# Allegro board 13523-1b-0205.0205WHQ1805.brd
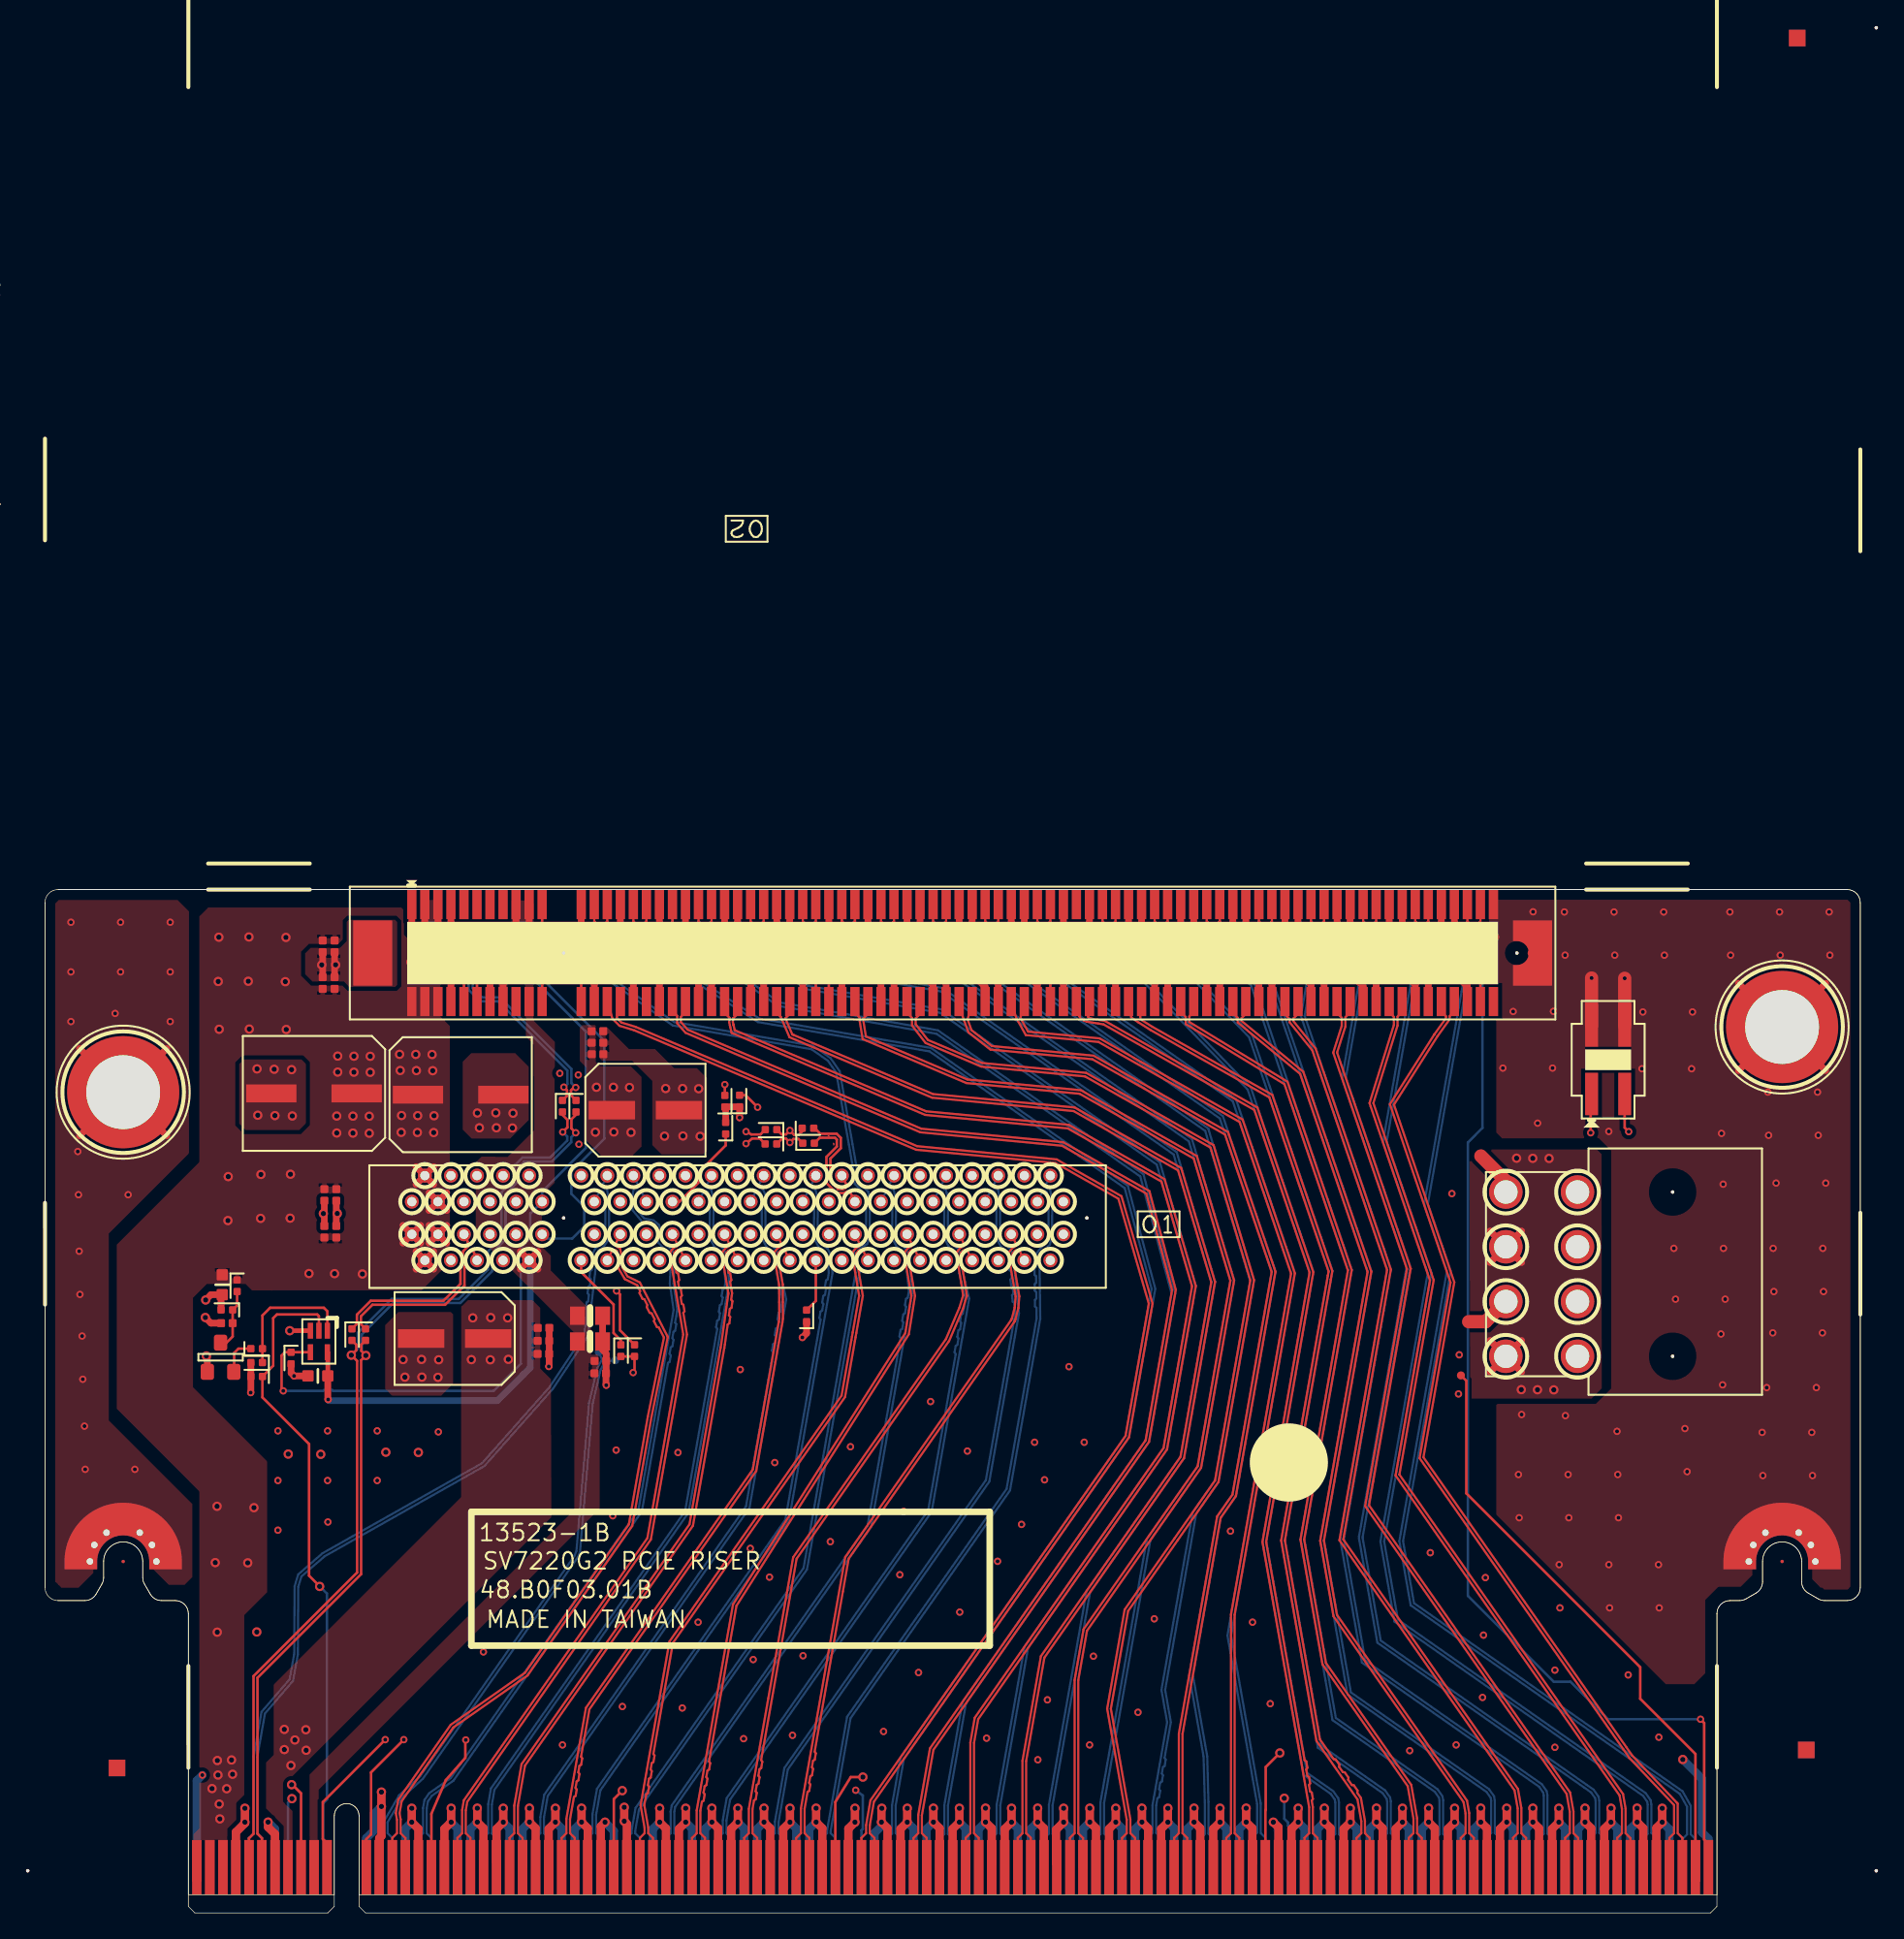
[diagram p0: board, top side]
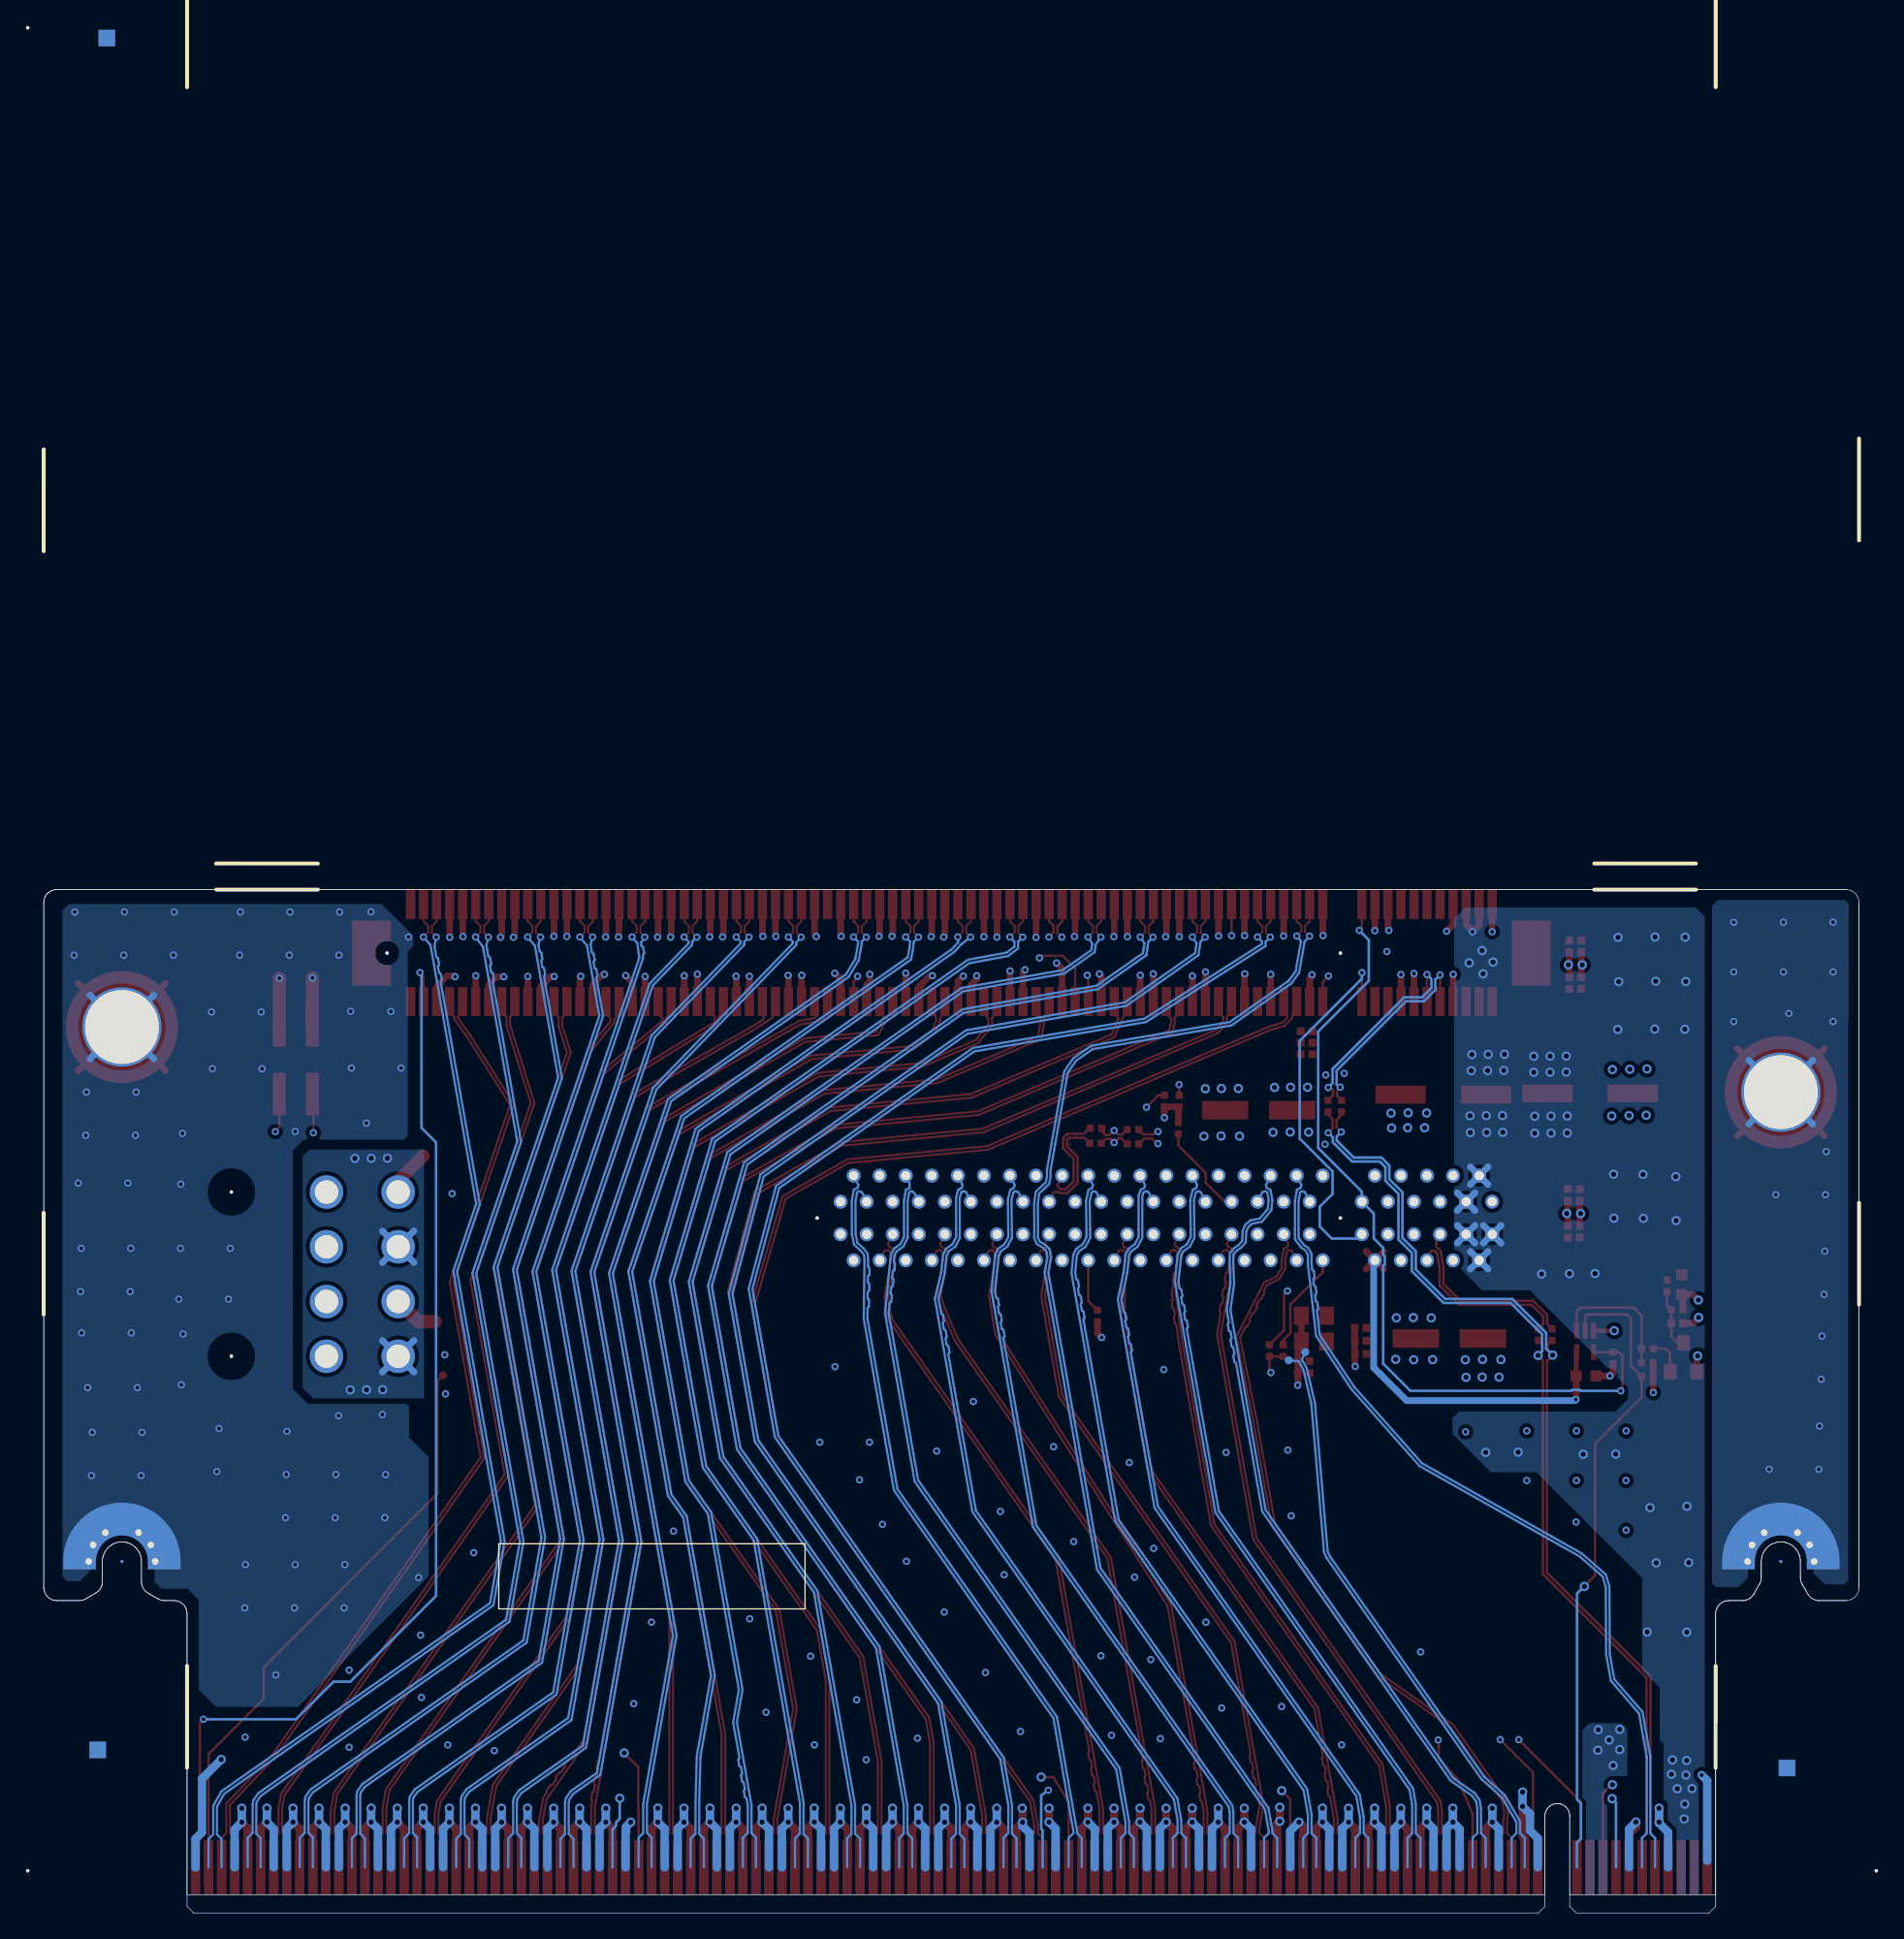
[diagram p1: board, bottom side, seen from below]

Outline 139.3 x 78.5 mm; copper layers: TOP, L2GND, L3, L4VCC, L5GND, BOTTOM. Coordinates in mm from the lower left corner of the outline.
Outline path: 0,77.5 0,24.96 ; 0,77.5 arc(0.29,78.21) 1,78.5 ; 0,77.5 0,24.96 ; 0,24.96 arc(0.29,24.25) 1,23.96 ; 1,78.5 138.3,78.5 ; 1,78.5 138.3,78.5 ; 138.3,78.5 arc(139.01,78.21) 139.3,77.5 ; 138.3,78.5 arc(139.01,78.21) 139.3,77.5 ; 1,23.96 3.06,23.96 ; 1,23.96 3.06,23.96 ; 3.06,23.96 arc(3.56,24.09) 3.92,24.46 ; 3.06,23.96 arc(3.56,24.09) 3.92,24.46 ; 3.92,24.46 4.37,25.23 ; 3.92,24.46 4.37,25.23 ; 4.37,25.23 arc(4.47,25.47) 4.5,25.73 ; 4.37,25.23 arc(4.47,25.47) 4.5,25.73 ; 4.5,26.96 4.5,25.73 ; 4.5,26.96 arc(6,28.46) 7.5,26.96 ; 4.5,26.96 arc(6,28.46) 7.5,26.96 ; 4.5,26.96 4.5,25.73 ; 7.5,26.96 7.5,25.73 ; 7.5,26.96 7.5,25.73 ; 7.5,25.73 arc(7.53,25.47) 7.63,25.23 ; 7.5,25.73 arc(7.53,25.47) 7.63,25.23 ; 7.63,25.23 8.08,24.46 ; 7.63,25.23 8.08,24.46 ; 8.08,24.46 arc(8.44,24.09) 8.94,23.96 ; 8.08,24.46 arc(8.44,24.09) 8.94,23.96 ; 8.94,23.96 10,23.96 ; 8.94,23.96 10,23.96 ; 10,23.96 arc(10.71,23.67) 11,22.96 ; 10,23.96 arc(10.71,23.67) 11,22.96 ; 11,22.96 11,1.4 22.2,1.4 22.2,7.45 ; 11,22.96 11,0.5 11.5,0 21.7,0 22.2,0.5 22.2,7.45 ; 22.2,7.45 arc(23.15,8.4) 24.1,7.45 ; 22.2,7.45 arc(23.15,8.4) 24.1,7.45 ; 24.1,7.45 24.1,1.4 128.3,1.4 128.3,22.96 ; 24.1,7.45 24.1,0.5 24.6,0 127.8,0 128.3,0.5 128.3,22.96 ; 128.3,22.96 arc(128.59,23.67) 129.3,23.96 ; 128.3,22.96 arc(128.59,23.67) 129.3,23.96 ; 129.3,23.96 130.03,23.96 ; 129.3,23.96 130.03,23.96 ; 130.03,23.96 arc(130.29,23.99) 130.53,24.09 ; 130.03,23.96 arc(130.29,23.99) 130.53,24.09 ; 130.53,24.09 131.3,24.54 ; 130.53,24.09 131.3,24.54 ; 131.3,24.54 arc(131.67,24.9) 131.8,25.4 ; 131.3,24.54 arc(131.67,24.9) 131.8,25.4 ; 131.8,26.96 131.8,25.4 ; 131.8,26.96 arc(133.3,28.46) 134.8,26.96 ; 131.8,26.96 arc(133.3,28.46) 134.8,26.96 ; 131.8,26.96 131.8,25.4 ; 134.8,26.96 134.8,25.4 ; 134.8,26.96 134.8,25.4 ; 134.8,25.4 arc(134.93,24.9) 135.3,24.54 ; 134.8,25.4 arc(134.93,24.9) 135.3,24.54 ; 135.3,24.54 136.07,24.09 ; 135.3,24.54 136.07,24.09 ; 136.07,24.09 arc(136.31,23.99) 136.57,23.96 ; 136.07,24.09 arc(136.31,23.99) 136.57,23.96 ; 136.57,23.96 138.3,23.96 ; 136.57,23.96 138.3,23.96 ; 138.3,23.96 arc(139.01,24.25) 139.3,24.96 ; 138.3,23.96 arc(139.01,24.25) 139.3,24.96 ; 139.3,77.5 139.3,24.96 ; 139.3,77.5 139.3,24.96

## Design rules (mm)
constraint set DEFAULT: min track width 0.127, pair gap 0.102
net group POWER-40: nets P5V-1 P5V-2
net group 50OHM_SIGNAL-MW: nets PCIE_CPRSNT_N PCIE_SLOT0_CPRSNT1_N PCIE_SLOT0_CPRSNT2_N PCIE_SLOT1_CPRSNT1_N PCIE_SLOT1_CPRSNT2_N PCIE_SLOT1_CPRSNT3_N PCIE_WAKE_N SLOT0_CONFIG SLOT0_ID_0 SLOT0_ID_1 SLOT1_CONFIG SLOT1_ID_0 SLOT1_ID_1
net group CRITICAL_50OHM_SIGNAL-MW: nets PCH_PLTRST_N PERST_LAT_N PERST_N RESET_IN RESET_O
net group I2C-MW: nets LAN_SMB_ALERT_N S0_SMB_ALERT_B12_N S1_SMB_ALERT_B12_N

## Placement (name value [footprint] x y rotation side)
C1  SCD1U25V2KX-GP  [C402H22]  22.35 52.26 180 top
C2  SCD1U25V2KX-GP  [C402H22]  21.44 55.08 0 top
C3  SCD1U25V2KX-GP  [C402H22]  21.44 52.26 180 top
C4  SCD1U25V2KX-GP  [C402H22]  22.35 55.08 0 top
C5  SCD1U16V2KX-3GP  [C402H22]  38.25 44.87 90 top
C6  SCD1U16V2KX-3GP  [C402H22]  38.24 42.88 90 top
C7  SCD1U16V2KX-3GP  [C402H22]  38.25 43.88 90 top
C8  SC10U6D3V5KX-4GP  [C805H58]  41.82 43.83 90 top
C9  SCD1U16V2KX-3GP  [C402H22]  42.62 42.34 90 top
C10  SCD1U25V2KX-GP  [C402H22]  21.31 74.15 0 top
C11  SCD1U25V2KX-GP  [C402H22]  22.23 74.15 0 top
C12  SCD1U25V2KX-GP  [C402H22]  21.31 71.33 180 top
C13  SCD1U25V2KX-GP  [C402H22]  22.23 71.33 180 top
C14  SCD1U16V2KX-3GP  [C402H22]  42.39 67.63 90 top
C15  SCD1U16V2KX-3GP  [C402H22]  42.4 65.87 90 top
C16  SCD1U16V2KX-3GP  [C402H22]  42.4 66.75 90 top
C17  SC10U6D3V5KX-4GP  [C805H58]  41.83 45.81 90 top
C18  SCD1U16V2KX-3GP  [C402H22]  42.61 41.39 90 top
C19  SCD01U16V2KX-L1-GP  [C402H22]  13.96 45.24 270 top
C20  SCD1U25V3KX-GP  [C603H36]  20.94 41.19 270 top
C21  SCD1U25V3KX-GP  [C603H36]  13.6 48.19 0 top
CFGCN1  AMP-CONN4A-2-GP  [G800MR594018EU]  119.95 65.45 180 top
CN1  TYCO-CONN98-4R-6-GP  [2-1612163-3]  39.8 53.31 0 top
CN2  PCISLT164-64-GP  [G630FAA2621EU]  39.8 73.63 0 top
CN3  ALP-CONN8B-GP  [C23106-108C0-L]  124.9 49 90 top
GF1  GF-PCIE-230P-GP  [GF-PCIE-230P]  23.15 1.4 0 top
H1  STFT339B239R223H453-GP  [STFT339B239R223H453]  133.3 67.96 0 top
H2  STFT339B239R223H453-GP  [STFT339B239R223H453]  6 62.96 0 top
H3  GEN276X162R197X296-6-F-A-GP  [GEN276X162R197X296-6-F-A]  133.3 26.96 0 top
H4  GEN276X162R197X296-6-F-A-GP  [GEN276X162R197X296-6-F-A]  6 26.96 0 top
NOREF  -  [unnamed]  135.16 12.5 0 top
NOREF#2  -  [unnamed]  140.53 144.61 0 top
NOREF#3  -  [#2]  0 23.96 0 top
NOREF#4  -  [#2]  0 23.96 0 top
NOREF#5  -  [#2]  95.45 34.55 0 top
NOREF#6  -  [unnamed]  -1.32 3.24 0 top
NOREF#7  -  [unnamed]  5.53 11.12 0 top
NOREF#8  -  [#2]  -5 138.58 0 top
NOREF#9  -  [unnamed]  134.46 143.82 0 top
NOREF#10  -  [#2]  85.46 52.82 0 top
NOREF#11  -  [#2]  0 23.96 0 top
NOREF#12  -  [#2]  53.84 106.18 180 top
NOREF#13  -  [#2]  0 23.96 0 top
NOREF#14  -  [unnamed]  140.53 3.24 0 top
NOREF#15  -  [#2]  5.61 149.39 0 top
NOREF#16  -  [#2]  0 23.96 0 top
NOREF#17  -  [#2]  0 23.96 0 top
NOREF#18  -  [unnamed]  135.16 12.5 180 bottom
NOREF#19  -  [unnamed]  5.53 11.12 180 bottom
NOREF#20  -  [unnamed]  134.46 143.82 180 bottom
R1  4K7R2D-GP  [R402H16]  14.74 48.11 0 top
R2  1K8R2D-GP  [R402H16]  13.96 46.26 270 top
R3  0R2J-2-GP  [R402H16]  16.24 43.29 90 top
R4  100KR2F-L1-GP  [R402H16]  16.24 42.22 270 top
R5  100KR2F-L1-GP  [R402H16]  16.24 41.15 270 top
R6  100KR2F-L1-GP  [R402H16]  18.88 42.57 0 top
R7  100R2J-L-GP  [R402H15]  52.23 60.2 180 top
R8  100R2J-L-GP  [R402H15]  58.44 45.8 180 top
R9  100R2J-L-GP  [R402H15]  52.17 62.27 180 top
R10  100R2J-L-GP  [R402H15]  53.3 62.28 180 top
RE1  0R2J-2-GP  [R402H16]  23.56 44.36 0 top
RE2  0R2J-2-GP  [R402H16]  58.55 60.19 90 top
RE3  0R2J-2-GP  [R402H16]  58.59 59.04 90 top
RE4  0R2J-2-GP  [R402H16]  44.19 43.13 0 top
RE5  0R2J-2-GP  [R402H16]  55.72 60.09 270 top
RE6  0R2J-2-GP  [R402H16]  55.71 58.99 270 top
RE7  0R2J-2-GP  [R402H16]  24.6 44.36 0 top
RE8  0R2J-2-GP  [R402H16]  45.24 43.14 0 top
RE9  0R2J-2-GP  [R402H16]  40.75 61.89 0 top
RE10  0R2J-2-GP  [R402H16]  39.71 61.89 0 top
TC1  SE270U16VM-2-GP  [SE391427H276]  20.64 62.86 270 top
TC2  SE220U6D3VM-8GP  [SE331721H237]  31.44 44.06 270 top
TC3  SE270U16VM-2-GP  [SE391427H276]  31.9 62.77 90 top
TC4  SE220U6D3VM-8GP  [SE331721H237]  46.07 61.58 90 top
TP1  -  [TPAD24]  42.49 43.02 180 bottom
TP2  -  [TPAD24]  43.76 42.39 180 bottom
TP3  -  [TPAD24]  108.66 41.23 0 top
TP4  -  [TPAD24]  110.19 58.06 0 top
TP5  -  [TPAD24]  109.25 45.35 0 top
U1  TPS3809K33-2-GP  [SOT-23-1H58]  13.47 42.63 0 top
U8  SNLVC1G08DCKRG4-GP  [SC70-5H44]  21.02 43.84 0 top

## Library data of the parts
C1-C4 C10-C13 = C402H22: tolerance: 78.10422.5FL
C5-C7 C9 C14-C16 C18 = C402H22: tolerance: 78.10421.2FL
C8 C17 = C805H58: tolerance: 78.10620.21L
C19 = C402H22: tolerance: 78.10321.L0L
C20 C21 = C603H36: tolerance: 78.10422.2BL
CFGCN1 = G800MR594018EU: tolerance: 21.D0408.202
CN1 = 2-1612163-3: tolerance: 20.50446.098
CN2 = G630FAA2621EU: tolerance: 20.C0083.164
CN3 = C23106-108C0-L: tolerance: 20.82113.008
GF1 = GF-PCIE-230P: tolerance: ZZ.GF001.711; alternate symbols: (TOP:GF-PCIE-230P)
H1 H2 = STFT339B239R223H453: tolerance: ZZ.SCREW.601
H3 H4 = GEN276X162R197X296-6-F-A: tolerance: ZZ.SCREW.511
R1 = R402H16: tolerance: 64.47016.6DL
R2 = R402H16: tolerance: 64.18016.6DL
R3 RE1-RE10 = R402H16: tolerance: 63.R0034.1DL
R4-R6 = R402H16: tolerance: 64.10035.6DL
R7-R10 = R402H15: tolerance: 63.10134.L0L
TC1 TC3 = SE391427H276: tolerance: 77.52771.01L
TC2 TC4 = SE331721H237: tolerance: 79.22710.E0L
TP1-TP5 = TPAD24: tolerance: ZZ.PAD24.001
U1 = SOT-23-1H58: tolerance: 74.03809.07B
U8 = SC70-5H44: tolerance: 73.01G08.DHG

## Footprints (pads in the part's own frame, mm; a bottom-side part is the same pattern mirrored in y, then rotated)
2-1612163-3
  round 0.254 hole 2.362 unplated: (0,0) (40.15,0)
  round 1.067 hole 0.711: A1(-11.65,1.25) A2(-10.65,3.25) A3(-9.649,1.25) A4(-8.65,3.25) A5(-7.65,1.25) A6(-6.65,3.25) A7(-5.65,1.25) A8(-4.649,3.25) A9(-3.65,1.25) A10(-2.65,3.25) A11(-1.65,1.25) A12(1.35,3.25) A13(2.349,1.25) A14(3.35,3.25) A15(4.35,1.25) A16(5.351,3.25) A17(6.35,1.25) A18(7.349,3.25) A19(8.35,1.25) A20(9.35,3.25) A21(10.351,1.25) A22(11.35,3.25) A23(12.349,1.25) A24(13.35,3.25) A25(14.35,1.25) A26(15.35,3.25) A27(16.35,1.25) A28(17.349,3.25) A29(18.35,1.25) A30(19.35,3.25) A31(20.35,1.25) A32(21.35,3.25) A33(22.349,1.25) A34(23.35,3.25) A35(24.35,1.25) A36(25.35,3.25) A37(26.35,1.25) A38(27.349,3.25) A39(28.35,1.25) A40(29.35,3.25) A41(30.35,1.25) A42(31.35,3.25) A43(32.349,1.25) A44(33.35,3.25) A45(34.35,1.25) A46(35.35,3.25) A47(36.35,1.25) A48(37.349,3.25) A49(38.35,1.25) B1(-11.65,-1.25) B2(-10.65,-3.25) B3(-9.649,-1.25) B4(-8.65,-3.25) B5(-7.65,-1.25) B6(-6.65,-3.25) B7(-5.65,-1.25) B8(-4.649,-3.25) B9(-3.65,-1.25) B10(-2.65,-3.25) B11(-1.65,-1.25) B12(1.35,-3.25) B13(2.349,-1.25) B14(3.35,-3.25) B15(4.35,-1.25) B16(5.351,-3.25) B17(6.35,-1.25) B18(7.349,-3.25) B19(8.35,-1.25) B20(9.35,-3.25) B21(10.351,-1.25) B22(11.35,-3.25) B23(12.349,-1.25) B24(13.35,-3.25) B25(14.35,-1.25) B26(15.35,-3.25) B27(16.35,-1.25) B28(17.349,-3.25) B29(18.35,-1.25) B30(19.35,-3.25) B31(20.35,-1.25) B32(21.35,-3.25) B33(22.349,-1.25) B34(23.35,-3.25) B35(24.35,-1.25) B36(25.35,-3.25) B37(26.35,-1.25) B38(27.349,-3.25) B39(28.35,-1.25) B40(29.35,-3.25) B41(30.35,-1.25) B42(31.35,-3.25) B43(32.349,-1.25) B44(33.35,-3.25) B45(34.35,-1.25) B46(35.35,-3.25) B47(36.35,-1.25) B48(37.349,-3.25) B49(38.35,-1.25)
C402H22
  custom 0.152x0.152 smd: 1(0,0.445) 2(0,-0.445)
C603H36
  custom 0.216x0.216 smd: 1(0,0.762) 2(0,-0.762)
C805H58
  rect 1.397x1.143 smd: 1(0,0.965) 2(0,-0.965)
C23106-108C0-L
  round 0.254 hole 3.023 unplated: (-6.3,0) (6.3,0)
  round 2.565 hole 1.803: 1(6.3,7.3) 2(2.1,7.3) 3(-2.1,7.3) 4(-6.3,7.3) 5(6.3,12.8) 6(2.1,12.8) 7(-2.1,12.8) 8(-6.3,12.8)
G630FAA2621EU
  round 0.254 hole 1.219 unplated: (0,0) (73.15,0)
  rect 2.997x5.004 smd: 165(-14.65,0)
  custom 0.749x0.749 smd: 166(74.35,0)
  rect 0.711x2.235 smd: A1(-11.65,3.718) A2(-10.65,3.718) A3(-9.65,3.718) A4(-8.65,3.718) A5(-7.65,3.718) A6(-6.65,3.718) A7(-5.65,3.718) A8(-4.65,3.718) A9(-3.65,3.718) A10(-2.65,3.718) A11(-1.65,3.718) A12(1.35,3.718) A13(2.35,3.718) A14(3.35,3.718) A15(4.35,3.718) A16(5.35,3.718) A17(6.35,3.718) A18(7.35,3.718) A19(8.35,3.718) A20(9.35,3.718) A21(10.35,3.718) A22(11.35,3.718) A23(12.35,3.718) A24(13.35,3.718) A25(14.35,3.718) A26(15.35,3.718) A27(16.35,3.718) A28(17.35,3.718) A29(18.35,3.718) A30(19.35,3.718) A31(20.35,3.718) A32(21.35,3.718) A33(22.35,3.718) A34(23.35,3.718) A35(24.35,3.718) A36(25.35,3.718) A37(26.35,3.718) A38(27.35,3.718) A39(28.35,3.718) A40(29.35,3.718) A41(30.35,3.718) A42(31.35,3.718) A43(32.35,3.718) A44(33.35,3.718) A45(34.35,3.718) A46(35.35,3.718) A47(36.35,3.718) A48(37.35,3.718) A49(38.35,3.718) A50(39.35,3.718) A51(40.35,3.718) A52(41.35,3.718) A53(42.35,3.718) A54(43.35,3.718) A55(44.35,3.718) A56(45.35,3.718) A57(46.35,3.718) A58(47.35,3.718) A59(48.35,3.718) A60(49.35,3.718) A61(50.35,3.718) A62(51.35,3.718) A63(52.35,3.718) A64(53.35,3.718) A65(54.35,3.718) A66(55.35,3.718) A67(56.35,3.718) A68(57.35,3.718) A69(58.35,3.718) A70(59.35,3.718) A71(60.35,3.718) A72(61.35,3.718) A73(62.35,3.718) A74(63.35,3.718) A75(64.35,3.718) A76(65.35,3.718) A77(66.35,3.718) A78(67.35,3.718) A79(68.35,3.718) A80(69.35,3.718) A81(70.35,3.718) A82(71.35,3.718) B1(-11.65,-3.718) B2(-10.65,-3.718) B3(-9.65,-3.718) B4(-8.65,-3.718) B5(-7.65,-3.718) B6(-6.65,-3.718) B7(-5.65,-3.718) B8(-4.65,-3.718) B9(-3.65,-3.718) B10(-2.65,-3.718) B11(-1.65,-3.718) B12(1.35,-3.718) B13(2.35,-3.718) B14(3.35,-3.718) B15(4.35,-3.718) B16(5.35,-3.718) B17(6.35,-3.718) B18(7.35,-3.718) B19(8.35,-3.718) B20(9.35,-3.718) B21(10.35,-3.718) B22(11.35,-3.718) B23(12.35,-3.718) B24(13.35,-3.718) B25(14.35,-3.718) B26(15.35,-3.718) B27(16.35,-3.718) B28(17.35,-3.718) B29(18.35,-3.718) B30(19.35,-3.718) B31(20.35,-3.718) B32(21.35,-3.718) B33(22.35,-3.718) B34(23.35,-3.718) B35(24.35,-3.718) B36(25.35,-3.718) B37(26.35,-3.718) B38(27.35,-3.718) B39(28.35,-3.718) B40(29.35,-3.718) B41(30.35,-3.718) B42(31.35,-3.718) B43(32.35,-3.718) B44(33.35,-3.718) B45(34.35,-3.718) B46(35.35,-3.718) B47(36.35,-3.718) B48(37.35,-3.718) B49(38.35,-3.718) B50(39.35,-3.718) B51(40.35,-3.718) B52(41.35,-3.718) B53(42.35,-3.718) B54(43.35,-3.718) B55(44.35,-3.718) B56(45.35,-3.718) B57(46.35,-3.718) B58(47.35,-3.718) B59(48.35,-3.718) B60(49.35,-3.718) B61(50.35,-3.718) B62(51.35,-3.718) B63(52.35,-3.718) B64(53.35,-3.718) B65(54.35,-3.718) B66(55.35,-3.718) B67(56.35,-3.718) B68(57.35,-3.718) B69(58.35,-3.718) B70(59.35,-3.718) B71(60.35,-3.718) B72(61.35,-3.718) B73(62.35,-3.718) B74(63.35,-3.718) B75(64.35,-3.718) B76(65.35,-3.718) B77(66.35,-3.718) B78(67.35,-3.718) B79(68.35,-3.718) B80(69.35,-3.718) B81(70.35,-3.718) B82(71.35,-3.718)
G800MR594018EU
  rect 0.991x3.251 smd: 1(1.27,2.625) 2(1.27,-2.625) 3(-1.27,2.625) 4(-1.27,-2.625)
GEN276X162R197X296-6-F-A
  round 0.254 hole 0.025 unplated: (0,0)
  round 0.864 hole 0.508: 1(2.55,0) 2(2.21,1.27) 3(1.27,2.21) 4(-1.28,2.21) 5(-2.21,1.27) 6(-2.55,0)
GF-PCIE-230P
  rect 0.711x3.2 smd: A1(-11.5,2.591) B114(103.5,2.591)
  rect 0.711x4.191 smd: A2(-10.5,2.095) A3(-9.5,2.095) A4(-8.5,2.095) A5(-7.5,2.095) A6(-6.5,2.095) A7(-5.5,2.095) A8(-4.5,2.095) A9(-3.5,2.095) A10(-2.5,2.095) A11(-1.5,2.095) A12(1.5,2.095) A13(2.5,2.095) A14(3.5,2.095) A15(4.5,2.095) A16(5.5,2.095) A17(6.5,2.095) A18(7.5,2.095) A19(8.5,2.095) A20(9.5,2.095) A21(10.5,2.095) A22(11.5,2.095) A23(12.5,2.095) A24(13.5,2.095) A25(14.5,2.095) A26(15.5,2.095) A27(16.5,2.095) A28(17.5,2.095) A29(18.5,2.095) A30(19.5,2.095) A31(20.5,2.095) A32(21.5,2.095) A33(22.5,2.095) A34(23.5,2.095) A35(24.5,2.095) A36(25.5,2.095) A37(26.5,2.095) A38(27.5,2.095) A39(28.5,2.095) A40(29.5,2.095) A41(30.5,2.095) A42(31.5,2.095) A43(32.5,2.095) A44(33.5,2.095) A45(34.5,2.095) A46(35.5,2.095) A47(36.5,2.095) A48(37.5,2.095) A49(38.5,2.095) A50(39.5,2.095) A51(40.5,2.095) A52(41.5,2.095) A53(42.5,2.095) A54(43.5,2.095) A55(44.5,2.095) A56(45.5,2.095) A57(46.5,2.095) A58(47.5,2.095) A59(48.5,2.095) A60(49.5,2.095) A61(50.5,2.095) A62(51.5,2.095) A63(52.5,2.095) A64(53.5,2.095) A65(54.5,2.095) A66(55.5,2.095) A67(56.5,2.095) A68(57.5,2.095) A69(58.5,2.095) A70(59.5,2.095) A71(60.5,2.095) A72(61.5,2.095) A73(62.5,2.095) A74(63.5,2.095) A75(64.5,2.095) A76(65.5,2.095) A77(66.5,2.095) A78(67.5,2.095) A79(68.5,2.095) A80(69.5,2.095) A81(70.5,2.095) A82(71.5,2.095) A83(72.5,2.095) A84(73.5,2.095) A85(74.5,2.095) A86(75.5,2.095) A87(76.5,2.095) A88(77.5,2.095) A89(78.5,2.095) A90(79.5,2.095) A91(80.5,2.095) A92(81.5,2.095) A93(82.5,2.095) A94(83.5,2.095) A95(84.5,2.095) A96(85.5,2.095) A97(86.5,2.095) A98(87.5,2.095) A99(88.5,2.095) A100(89.5,2.095) A101(90.5,2.095) A102(91.5,2.095) A103(92.5,2.095) A104(93.5,2.095) A105(94.5,2.095) A106(95.5,2.095) A107(96.5,2.095) A108(97.5,2.095) A109(98.5,2.095) A110(99.5,2.095) A111(100.5,2.095) A112(101.5,2.095) A113(102.5,2.095) A114(103.5,2.095) A115(104.5,2.095) B1(-11.5,2.349) B2(-10.5,2.349) B3(-9.5,2.349) B4(-8.5,2.349) B5(-7.5,2.349) B6(-6.5,2.349) B7(-5.5,2.349) B8(-4.5,2.349) B9(-3.5,2.349) B10(-2.5,2.349) B11(-1.5,2.349) B12(1.5,2.349) B13(2.5,2.349) B14(3.5,2.349) B15(4.5,2.349) B16(5.5,2.349) B17(6.5,2.349) B18(7.5,2.349) B19(8.5,2.349) B20(9.5,2.349) B21(10.5,2.349) B22(11.5,2.349) B23(12.5,2.349) B24(13.5,2.349) B25(14.5,2.349) B26(15.5,2.349) B27(16.5,2.349) B28(17.5,2.349) B29(18.5,2.349) B30(19.5,2.349) B31(20.5,2.349) B32(21.5,2.349) B33(22.5,2.349) B34(23.5,2.349) B35(24.5,2.349) B36(25.5,2.349) B37(26.5,2.349) B38(27.5,2.349) B39(28.5,2.349) B40(29.5,2.349) B41(30.5,2.349) B42(31.5,2.349) B43(32.5,2.349) B44(33.5,2.349) B45(34.5,2.349) B46(35.5,2.349) B47(36.5,2.349) B48(37.5,2.349) B49(38.5,2.349) B50(39.5,2.349) B51(40.5,2.349) B52(41.5,2.349) B53(42.5,2.349) B54(43.5,2.349) B55(44.5,2.349) B56(45.5,2.349) B57(46.5,2.349) B58(47.5,2.349) B59(48.5,2.349) B60(49.5,2.349) B61(50.5,2.349) B62(51.5,2.349) B63(52.5,2.349) B64(53.5,2.349) B65(54.5,2.349) B66(55.5,2.349) B67(56.5,2.349) B68(57.5,2.349) B69(58.5,2.349) B70(59.5,2.349) B71(60.5,2.349) B72(61.5,2.349) B73(62.5,2.349) B74(63.5,2.349) B75(64.5,2.349) B76(65.5,2.349) B77(66.5,2.349) B78(67.5,2.349) B79(68.5,2.349) B80(69.5,2.349) B81(70.5,2.349) B82(71.5,2.349) B83(72.5,2.349) B84(73.5,2.349) B85(74.5,2.349) B86(75.5,2.349) B87(76.5,2.349) B88(77.5,2.349) B89(78.5,2.349) B90(79.5,2.349) B91(80.5,2.349) B92(81.5,2.349) B93(82.5,2.349) B94(83.5,2.349) B95(84.5,2.349) B96(85.5,2.349) B97(86.5,2.349) B98(87.5,2.349) B99(88.5,2.349) B100(89.5,2.349) B101(90.5,2.349) B102(91.5,2.349) B103(92.5,2.349) B104(93.5,2.349) B105(94.5,2.349) B106(95.5,2.349) B107(96.5,2.349) B108(97.5,2.349) B109(98.5,2.349) B110(99.5,2.349) B111(100.5,2.349) B112(101.5,2.349) B113(102.5,2.349) B115(104.5,2.349)
R402H15
  custom 0.14x0.14 smd: 1(0,0.445) 2(0,-0.445)
R402H16
  custom 0.14x0.14 smd: 1(0,0.445) 2(0,-0.445)
SC70-5H44
  rect 0.406x1.219 smd: 1(0.65,0.826) 2(0,0.826) 3(-0.65,0.826) 4(-0.65,-0.826) 5(0.65,-0.826)
SE331721H237
  rect 1.422x3.556 smd: 1(0,2.574) 2(0,-2.574)
SE391427H276
  rect 1.372x3.861 smd: 1(0,3.276) 2(0,-3.276)
SOT-23-1H58
  custom 0.254x0.254 smd: 1(-1.016,-1.118) 2(1.016,-1.118) 3(0,1.118)
STFT339B239R223H453
  round 8.611 hole 5.664: 1(0,0)
TPAD24
  round 0.61 smd: 1(0,0)
unnamed
  rect 1.27x1.27 smd: (0,0)

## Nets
GND: C1.2 C2.2 C3.2 C4.2 C5.2 C6.2 C7.2 C8.2 C9.2 C10.2 C11.2 C12.2 C13.2 C14.2 C15.2 C16.2 C17.2 C18.2 C19.2 C20.2 C21.2 CFGCN1.2 CFGCN1.4 CN1.A1 CN1.A4 CN1.A12 CN1.A15 CN1.A18 CN1.A20 CN1.A23 CN1.A24 CN1.A27 CN1.A28 CN1.A31 CN1.A34 CN1.A37 CN1.A38 CN1.A41 CN1.A42 CN1.A45 CN1.A46 CN1.A49 CN1.B4 CN1.B7 CN1.B13 CN1.B16 CN1.B18 CN1.B21 CN1.B22 CN1.B25 CN1.B26 CN1.B29 CN1.B32 CN1.B35 CN1.B36 CN1.B39 CN1.B40 CN1.B43 CN1.B44 CN1.B47 CN1.B49 CN2.165 CN2.166 CN2.A1 CN2.A4 CN2.A12 CN2.A15 CN2.A18 CN2.A20 CN2.A23 CN2.A24 CN2.A27 CN2.A28 CN2.A31 CN2.A34 CN2.A37 CN2.A38 CN2.A41 CN2.A42 CN2.A45 CN2.A46 CN2.A49 CN2.A51 CN2.A54 CN2.A55 CN2.A58 CN2.A59 CN2.A62 CN2.A63 CN2.A66 CN2.A67 CN2.A70 CN2.A71 CN2.A74 CN2.A75 CN2.A78 CN2.A79 CN2.A82 CN2.B4 CN2.B7 CN2.B13 CN2.B16 CN2.B18 CN2.B21 CN2.B22 CN2.B25 CN2.B26 CN2.B29 CN2.B32 CN2.B35 CN2.B36 CN2.B39 CN2.B40 CN2.B43 CN2.B44 CN2.B47 CN2.B49 CN2.B52 CN2.B53 CN2.B56 CN2.B57 CN2.B60 CN2.B61 CN2.B64 CN2.B65 CN2.B68 CN2.B69 CN2.B72 CN2.B73 CN2.B76 CN2.B77 CN2.B80 CN3.1 CN3.2 CN3.3 CN3.4 GF1.A1 GF1.A4 GF1.A7 GF1.A12 GF1.A15 GF1.A18 GF1.A19 GF1.A20 GF1.A23 GF1.A24 GF1.A27 GF1.A28 GF1.A31 GF1.A34 GF1.A37 GF1.A38 GF1.A41 GF1.A42 GF1.A45 GF1.A46 GF1.A49 GF1.A51 GF1.A54 GF1.A55 GF1.A58 GF1.A59 GF1.A62 GF1.A63 GF1.A66 GF1.A67 GF1.A70 GF1.A71 GF1.A74 GF1.A75 GF1.A78 GF1.A79 GF1.A82 GF1.A84 GF1.A85 GF1.A88 GF1.A89 GF1.A92 GF1.A93 GF1.A96 GF1.A97 GF1.A100 GF1.A101 GF1.A104 GF1.A105 GF1.A108 GF1.A109 GF1.A112 GF1.A115 GF1.B4 GF1.B7 GF1.B13 GF1.B16 GF1.B18 GF1.B21 GF1.B22 GF1.B25 GF1.B26 GF1.B29 GF1.B30 GF1.B32 GF1.B35 GF1.B36 GF1.B39 GF1.B40 GF1.B43 GF1.B44 GF1.B47 GF1.B49 GF1.B52 GF1.B53 GF1.B56 GF1.B57 GF1.B60 GF1.B61 GF1.B64 GF1.B65 GF1.B68 GF1.B69 GF1.B72 GF1.B73 GF1.B76 GF1.B77 GF1.B80 GF1.B82 GF1.B83 GF1.B86 GF1.B87 GF1.B90 GF1.B91 GF1.B94 GF1.B95 GF1.B98 GF1.B99 GF1.B102 GF1.B103 GF1.B106 GF1.B107 GF1.B110 GF1.B111 H1.1 H2.1 H3.1 H3.2 H3.3 H3.4 H3.5 H3.6 H4.1 H4.2 H4.3 H4.4 H4.5 H4.6 R2.2 R4.2 R5.2 R6.2 R7.2 R8.1 R9.1 R10.1 TC1.2 TC2.2 TC3.2 TC4.2 U1.1 U8.3
P3V3: C5.1 C6.1 C7.1 C14.1 C15.1 C16.1 CN1.A9 CN1.A10 CN1.B8 CN2.A9 CN2.A10 CN2.B8 GF1.A9 GF1.A10 GF1.B8 TC2.1 TC4.1
P3V3_AUX: C8.1 C9.1 C17.1 C18.1 C20.1 CN1.B10 CN2.B10 GF1.B10 U8.5
P5V-1: CN3.5 TP4.1
P5V-2: CN3.7 TP5.1
P12V: C1.1 C2.1 C3.1 C4.1 C10.1 C11.1 C12.1 C13.1 C21.1 CN1.A2 CN1.A3 CN1.B1 CN1.B2 CN1.B3 CN2.A2 CN2.A3 CN2.B1 CN2.B2 CN2.B3 CN3.6 CN3.8 GF1.A2 GF1.A3 GF1.B1 GF1.B2 GF1.B3 R1.1 TC1.1 TC3.1
CLK100_PCIE_SLOT0_N: CN1.A14 GF1.A6
CLK100_PCIE_SLOT0_P: CN1.A13 GF1.A5
CLK100_PCIE_SLOT1_N: CN2.A14 GF1.A33
CLK100_PCIE_SLOT1_P: CN2.A13 GF1.A32
CLK100_PCIE_SLOT_N: GF1.A14 TP2.1
CLK100_PCIE_SLOT_P: GF1.A13 TP1.1
LAN_SMB_ALERT_N: GF1.B12 RE4.2 RE8.2
LAN_SMB_CLK: GF1.B9 RE2.1 RE5.1
LAN_SMB_DAT: GF1.A8 RE3.1 RE6.1
PCH_PLTRST_N: GF1.A11 R5.1 U8.2
PCIE_CPRSNT_N: GF1.B114 TP3.1
PCIE_SLOT0_CPRSNT1_N: CN1.B31 GF1.B17
PCIE_SLOT0_CPRSNT2_N: CN1.B48 GF1.B31
PCIE_SLOT0_RXN0: CN1.A48 GF1.A48
PCIE_SLOT0_RXN1: CN1.A44 GF1.A44
PCIE_SLOT0_RXN2: CN1.A40 GF1.A40
PCIE_SLOT0_RXN3: CN1.A36 GF1.A36
PCIE_SLOT0_RXN4: CN1.A30 GF1.A30
PCIE_SLOT0_RXN5: CN1.A26 GF1.A26
PCIE_SLOT0_RXN6: CN1.A22 GF1.A22
PCIE_SLOT0_RXN7: CN1.A17 GF1.A17
PCIE_SLOT0_RXP0: CN1.A47 GF1.A47
PCIE_SLOT0_RXP1: CN1.A43 GF1.A43
PCIE_SLOT0_RXP2: CN1.A39 GF1.A39
PCIE_SLOT0_RXP3: CN1.A35 GF1.A35
PCIE_SLOT0_RXP4: CN1.A29 GF1.A29
PCIE_SLOT0_RXP5: CN1.A25 GF1.A25
PCIE_SLOT0_RXP6: CN1.A21 GF1.A21
PCIE_SLOT0_RXP7: CN1.A16 GF1.A16
PCIE_SLOT0_TXN0: CN1.B46 GF1.B46
PCIE_SLOT0_TXN1: CN1.B42 GF1.B42
PCIE_SLOT0_TXN2: CN1.B38 GF1.B38
PCIE_SLOT0_TXN3: CN1.B34 GF1.B34
PCIE_SLOT0_TXN4: CN1.B28 GF1.B28
PCIE_SLOT0_TXN5: CN1.B24 GF1.B24
PCIE_SLOT0_TXN6: CN1.B20 GF1.B20
PCIE_SLOT0_TXN7: CN1.B15 GF1.B15
PCIE_SLOT0_TXP0: CN1.B45 GF1.B45
PCIE_SLOT0_TXP1: CN1.B41 GF1.B41
PCIE_SLOT0_TXP2: CN1.B37 GF1.B37
PCIE_SLOT0_TXP3: CN1.B33 GF1.B33
PCIE_SLOT0_TXP4: CN1.B27 GF1.B27
PCIE_SLOT0_TXP5: CN1.B23 GF1.B23
PCIE_SLOT0_TXP6: CN1.B19 GF1.B19
PCIE_SLOT0_TXP7: CN1.B14 GF1.B14
PCIE_SLOT1_CPRSNT1_N: CN2.B31 GF1.B48
PCIE_SLOT1_CPRSNT2_N: CN2.B48 GF1.B81
PCIE_SLOT1_CPRSNT3_N: CN2.B81 GF1.B115
PCIE_SLOT1_RXN0: CN2.A17 GF1.A53
PCIE_SLOT1_RXN1: CN2.A22 GF1.A57
PCIE_SLOT1_RXN2: CN2.A26 GF1.A61
PCIE_SLOT1_RXN3: CN2.A30 GF1.A65
PCIE_SLOT1_RXN4: CN2.A36 GF1.A69
PCIE_SLOT1_RXN5: CN2.A40 GF1.A73
PCIE_SLOT1_RXN6: CN2.A44 GF1.A77
PCIE_SLOT1_RXN7: CN2.A48 GF1.A81
PCIE_SLOT1_RXN8: CN2.A53 GF1.A87
PCIE_SLOT1_RXN9: CN2.A57 GF1.A91
PCIE_SLOT1_RXN10: CN2.A61 GF1.A95
PCIE_SLOT1_RXN11: CN2.A65 GF1.A99
PCIE_SLOT1_RXN12: CN2.A69 GF1.A103
PCIE_SLOT1_RXN13: CN2.A73 GF1.A107
PCIE_SLOT1_RXN14: CN2.A77 GF1.A111
PCIE_SLOT1_RXN15: CN2.A81 GF1.A114
PCIE_SLOT1_RXP0: CN2.A16 GF1.A52
PCIE_SLOT1_RXP1: CN2.A21 GF1.A56
PCIE_SLOT1_RXP2: CN2.A25 GF1.A60
PCIE_SLOT1_RXP3: CN2.A29 GF1.A64
PCIE_SLOT1_RXP4: CN2.A35 GF1.A68
PCIE_SLOT1_RXP5: CN2.A39 GF1.A72
PCIE_SLOT1_RXP6: CN2.A43 GF1.A76
PCIE_SLOT1_RXP7: CN2.A47 GF1.A80
PCIE_SLOT1_RXP8: CN2.A52 GF1.A86
PCIE_SLOT1_RXP9: CN2.A56 GF1.A90
PCIE_SLOT1_RXP10: CN2.A60 GF1.A94
PCIE_SLOT1_RXP11: CN2.A64 GF1.A98
PCIE_SLOT1_RXP12: CN2.A68 GF1.A102
PCIE_SLOT1_RXP13: CN2.A72 GF1.A106
PCIE_SLOT1_RXP14: CN2.A76 GF1.A110
PCIE_SLOT1_RXP15: CN2.A80 GF1.A113
PCIE_SLOT1_TXN0: CN2.B15 GF1.B51
PCIE_SLOT1_TXN1: CN2.B20 GF1.B55
PCIE_SLOT1_TXN2: CN2.B24 GF1.B59
PCIE_SLOT1_TXN3: CN2.B28 GF1.B63
PCIE_SLOT1_TXN4: CN2.B34 GF1.B67
PCIE_SLOT1_TXN5: CN2.B38 GF1.B71
PCIE_SLOT1_TXN6: CN2.B42 GF1.B75
PCIE_SLOT1_TXN7: CN2.B46 GF1.B79
PCIE_SLOT1_TXN8: CN2.B51 GF1.B85
PCIE_SLOT1_TXN9: CN2.B55 GF1.B89
PCIE_SLOT1_TXN10: CN2.B59 GF1.B93
PCIE_SLOT1_TXN11: CN2.B63 GF1.B97
PCIE_SLOT1_TXN12: CN2.B67 GF1.B101
PCIE_SLOT1_TXN13: CN2.B71 GF1.B105
PCIE_SLOT1_TXN14: CN2.B75 GF1.B109
PCIE_SLOT1_TXN15: CN2.B79 GF1.B113
PCIE_SLOT1_TXP0: CN2.B14 GF1.B50
PCIE_SLOT1_TXP1: CN2.B19 GF1.B54
PCIE_SLOT1_TXP2: CN2.B23 GF1.B58
PCIE_SLOT1_TXP3: CN2.B27 GF1.B62
PCIE_SLOT1_TXP4: CN2.B33 GF1.B66
PCIE_SLOT1_TXP5: CN2.B37 GF1.B70
PCIE_SLOT1_TXP6: CN2.B41 GF1.B74
PCIE_SLOT1_TXP7: CN2.B45 GF1.B78
PCIE_SLOT1_TXP8: CN2.B50 GF1.B84
PCIE_SLOT1_TXP9: CN2.B54 GF1.B88
PCIE_SLOT1_TXP10: CN2.B58 GF1.B92
PCIE_SLOT1_TXP11: CN2.B62 GF1.B96
PCIE_SLOT1_TXP12: CN2.B66 GF1.B100
PCIE_SLOT1_TXP13: CN2.B70 GF1.B104
PCIE_SLOT1_TXP14: CN2.B74 GF1.B108
PCIE_SLOT1_TXP15: CN2.B78 GF1.B112
PCIE_SMCLK: GF1.B5 RE1.2 RE10.2
PCIE_SMDAT: GF1.B6 RE7.2 RE9.2
PCIE_WAKE_N: CN1.B11 CN2.B11 GF1.B11
PERST_LAT_N: R3.2 R4.1 U8.1
PERST_N: CN1.A11 CN2.A11 R6.1 U8.4
RESET_IN: C19.1 R1.2 R2.1 U1.3
RESET_O: R3.1 U1.2
S0_PCIE_SMCLK: CN1.B5 RE1.1
S0_PCIE_SMDAT: CN1.B6 RE7.1
S0_SMB_ALERT_B12_N: CN1.B12 RE4.1
S0_SMB_CLK_A32: CN1.A32 RE2.2
S0_SMB_DAT_A33: CN1.A33 RE3.2
S1_PCIE_SMCLK: CN2.B5 RE10.1
S1_PCIE_SMDAT: CN2.B6 RE9.1
S1_SMB_ALERT_B12_N: CN2.B12 RE8.1
S1_SMB_CLK_A32: CN2.A32 RE5.2
S1_SMB_DAT_A33: CN2.A33 RE6.2
SLOT0_CONFIG: CFGCN1.1 GF1.A50
SLOT0_ID_0: CN1.A19 R7.1
SLOT0_ID_1: CN1.B30 R8.2
SLOT1_CONFIG: CFGCN1.3 GF1.A83
SLOT1_ID_0: CN2.A19 R9.2
SLOT1_ID_1: CN2.B30 R10.2

Pads without a net: CN1 A5 A6 A7 A8 B9 B17; CN2 A5 A6 A7 A8 A50 B9 B17 B82

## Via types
v1: diameter 0.711, hole 0.406, TOP to BOTTOM, 229 vias
v2: diameter 0.559, hole 0.305, TOP to BOTTOM, 301 vias

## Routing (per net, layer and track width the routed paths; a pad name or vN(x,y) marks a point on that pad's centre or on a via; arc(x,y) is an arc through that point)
GND: length 912.4
  TOP w0.356: v1(18.78,44.66) U8.3
  TOP w0.508: v2(55.15,71.93) 55.15,71.93 CN2.B26 ; v2(75.2,74.92) 75.15,74.97 CN2.A46 ; v2(100.15,74.91) 100.15,74.91 CN2.A71 ; CN2.B61 90.15,71.76 90.15,71.76 v2(90.15,71.89) ; C2.2 21.44,53.72 v1(21.36,53.65) 21.44,53.57 C3.2 ; CN2.A59 88.15,74.92 v2(88.2,74.86) ; H2.1 9.35,66.31 ; H2.1 2.65,66.31 ; H2.1 2.65,59.61 ; H2.1 9.35,59.61 ; CN2.A23 52.15,74.89 v2(52.16,74.88) ; CN2.B13 42.15,71.66 41.98,71.84 v2(41.98,71.97) ; v2(58.12,44.14) 58.44,44.47 R8.1 ; CN2.B49 78.15,71.66 78.58,72.08 v2(78.6,72.08) ; v2(45.14,72) 45.14,71.86 45.15,71.85 CN2.B16 ; v2(78.11,74.91) 78.15,74.96 CN2.A49 ; CN2.B73 v2(102.15,71.84) ; v2(80.02,74.9) 80.15,75.03 CN2.A51 ; v2(61.58,72.86) 61.15,72.43 CN2.B32 ; CN2.A20 49.15,74.94 v2(49.15,74.94) ; v1(12.38,42.73) 12.46,42.65 U1.1 ; CN2.B39 68.15,71.18 67.7,71.63 v2(67.7,71.89) ; 129.95,64.61 H1.1 ; H1.1 129.95,71.31 ; H1.1 136.65,64.61 ; H1.1 136.65,71.31 ; CN2.B68 97.15,71.23 96.39,71.99 v2(96.27,71.99) ; CN2.B18 47.15,71.81 47.14,71.83 v2(47.14,72.04) ; CN2.A37 66.15,74.92 66.15,74.92 v2(66.15,74.85) ; CN2.A24 53.15,74.94 v2(53.21,74.88) ; CN2.A67 96.15,74.9 v2(96.19,74.86) ; CN2.B4 31.15,71.99 v2(31.14,72) ; v2(84.12,74.91) 84.15,74.94 CN2.A55 ; v2(63.15,74.84) 63.15,74.84 CN2.A34 ; v2(81.13,71.92) 81.15,71.91 CN2.B52 ; C13.2 22.23,72.65 v1(22.3,72.73) 22.23,72.81 C11.2 ; v2(43.07,40.48) 43.07,40.56 43.05,40.58 C18.2 43.06,41.41 C9.2 43.06,42.84 43.04,42.96 42.79,43.21 C8.2 C17.2 ; v2(94.64,71.9) 94.15,71.42 CN2.B65 ; CN2.B35 64.15,72.19 v2(64,72.34) ; v2(70.24,74.86) 70.15,74.95 CN2.A41 ; CN2.A54 83.15,74.93 v2(83.12,74.91) ; v2(100.13,71.83) 100.41,71.83 101.15,71.09 CN2.B72 ; CN2.B40 69.15,71.45 68.74,71.86 v2(68.73,71.86) ; v2(106.14,71.89) 106.15,71.89 CN2.B77 ; CN2.A28 57.15,74.92 v2(57.18,74.89) ; C5.2 38.7,43.89 C7.2 38.69,42.89 C6.2 38.69,41.94 v2(38.66,41.92) ; v2(92.19,74.85) 92.15,74.89 CN2.A63 ; CN2.B53 82.15,71.89 v2(82.18,71.92) ; C19.2 12.74,45.24 v1(12.31,45.67) ; v2(99.16,74.91) 99.15,74.92 CN2.A70 ; CN2.A12 41.15,75.39 41.13,75.37 v2(41.13,74.97) ; CN2.B80 109.15,71.07 108.34,71.88 107.87,71.88 107.82,71.82 v2(107.73,71.82) ; v2(98.1,71.85) 98.15,71.8 CN2.B69 ; R4.2 R5.2 15.8,39.93 v2(15.78,39.91) ; CN2.B29 58.15,71.9 v2(58.29,72.03) ; v2(71.1,71.89) 71.29,71.89 72.15,71.03 CN2.B43 ; v2(60.21,74.9) 60.15,74.96 CN2.A31 ; v2(65.14,72.26) 65.14,72.23 65.15,72.22 CN2.B36 ; R2.2 13.51,47.34 C21.2 12.74,47.43 v1(12.33,47.02) ; v2(31.65,75.3) 31.15,75.8 CN2.A4 ; CN2.A62 91.15,74.9 v2(91.2,74.85) ; CN2.A38 67.15,74.89 v2(67.16,74.88) ; v2(75.91,72) 75.91,71.43 76.15,71.19 CN2.B47 ; C10.2 21.31,72.8 v1(21.24,72.72) 21.31,72.65 C12.2 ; CN2.B21 v2(50.15,72.19) ; CN2.A42 71.15,74.94 v2(71.2,74.89) ; CN2.A18 v2(47.15,74.97) ; CN2.A1 v2(28.15,75.26) ; CN2.A45 74.15,74.98 v2(74.21,74.92) ; CN2.A15 44.15,75.39 44.15,75.38 v2(44.15,74.94) ; C4.2 22.35,53.73 v1(22.43,53.65) 22.35,53.58 C1.2 ; R6.2 18.88,41.42 v2(19.11,41.19) C20.2 ; CN2.A79 108.15,74.84 v2(108.15,74.84) ; CN2.B56 v2(85.15,71.84) ; CN2.B60 89.15,71.85 89.14,71.86 v2(89.14,72.01) ; CN2.B7 v2(34.15,72.06) ; CN2.A27 56.15,74.9 v2(56.14,74.89) ; CN2.B57 86.15,71.83 v2(86.18,71.86) ; CN2.B64 v2(93.15,71.84) ; v2(104.25,74.84) 104.15,74.94 CN2.A75 ; v2(51.15,71.87) 51.15,71.87 CN2.B22 ; CN2.A78 107.15,74.92 v2(107.13,74.89) ; CN2.A58 87.15,74.92 v2(87.21,74.86) ; v2(103.26,74.84) 103.15,74.95 CN2.A74 ; CN2.B76 105.15,71.21 104.55,71.82 v2(104,71.82) ; v2(73.15,72.09) 73.15,71.63 73.15,71.63 CN2.B44 ; R7.2 52.23,61.76 R9.1 52.18,61.84 R10.1 v2(53.3,61.01) ; v2(95.19,74.86) 95.15,74.91 CN2.A66 ; v2(54.16,72.04) 54.16,71.95 54.15,71.94 CN2.B25
  TOP w0.635: v1(124.1,8.03) v1(124.1,6.96) 123.65,6.51 GF1.B111 ; v1(116.17,8.03) v1(116.17,6.96) 115.65,6.45 GF1.B103 ; GF1.B72 84.65,6.49 v1(84.17,6.97) v1(84.17,8.03) ; v1(35.17,8.03) v1(35.17,6.96) 34.65,6.45 GF1.B22 ; GF1.B26 38.65,6.45 v1(39.17,6.96) v1(39.17,8.03) ; v1(33.17,8.03) v1(33.17,6.97) 33.65,6.49 GF1.B21 ; v1(86.17,8.03) v1(86.17,6.96) 85.65,6.45 GF1.B73 ; GF1.B29 41.65,6.49 v1(41.17,6.97) v1(41.17,8.03) ; GF1.B40 52.65,6.45 v1(53.17,6.96) v1(53.17,8.03) ; v1(44.45,8.11) v1(44.45,7.04) 44.65,6.84 GF1.B32 ; v1(118.17,8.03) v1(118.17,6.97) 118.65,6.49 GF1.B106 ; v1(102.17,8.03) v1(102.17,6.97) 102.65,6.49 GF1.B90 ; v1(106.17,8.03) v1(106.17,6.97) 106.65,6.49 GF1.B94 ; v1(66.17,8.03) v1(66.17,6.96) 65.65,6.45 GF1.B53 ; GF1.B52 64.65,6.5 v1(64.19,6.96) 64.19,8 v1(64.21,8.03) ; GF1.B86 98.65,6.49 v1(98.17,6.97) v1(98.17,8.03) ; v1(80.17,8.03) v1(80.17,6.97) 80.65,6.49 GF1.B68 ; GF1.B16 28.65,6.46 v1(28.14,6.96) v1(28.14,8.03) ; v1(47.17,8.03) v1(47.17,6.96) 47.65,6.48 GF1.B35 ; v1(78.17,8.03) v1(78.17,6.96) 77.58,6.38 77.58,3.82 GF1.B65 ; GF1.B4 14.65,6.19 15.34,6.89 v1(15.34,6.96) v1(15.34,8.03) ; v1(88.17,8.03) v1(88.17,6.97) 88.65,6.49 GF1.B76 ; GF1.B91 103.65,6.45 v1(104.17,6.96) v1(104.17,8.03) ; v1(70.17,8.03) v1(70.17,6.96) 69.65,6.45 GF1.B57 ; v1(42.98,6.96) 42.65,6.64 GF1.B30 ; v1(112.17,8.03) v1(112.17,6.96) 111.65,6.45 GF1.B99 ; v1(76.17,8.03) v1(76.17,6.97) 76.65,6.49 GF1.B64 ; GF1.B18 30.65,6.45 v1(31.17,6.96) v1(31.17,8.03) ; GF1.B49 61.65,6.46 v1(62.15,6.96) v1(62.15,8.03) ; v1(94.26,6.96) 94.65,6.57 GF1.B82 ; v1(25.82,9.27) v1(25.82,8.17) 25.82,5.9 25.65,5.73 GF1.B13 ; GF1.B39 51.65,6.49 v1(51.17,6.97) v1(51.17,8.03) ; GF1.B43 55.65,6.49 v1(55.17,6.97) v1(55.17,8.03) ; v1(96.17,8.03) v1(96.17,6.96) 95.65,6.45 GF1.B83 ; GF1.B107 119.65,6.45 v1(120.17,6.96) v1(120.17,8.03) ; GF1.B98 110.65,6.49 v1(110.17,6.97) v1(110.17,8.03) ; GF1.B47 59.65,6.49 v1(59.17,6.97) v1(59.17,8.03) ; GF1.B77 89.65,6.45 v1(90.17,6.96) v1(90.17,8.03) ; v1(57.17,8.03) v1(57.17,6.96) 56.65,6.45 GF1.B44 ; GF1.B80 92.65,6.49 v1(92.17,6.97) v1(92.17,8.03) ; v1(72.17,8.03) v1(72.17,6.97) 72.65,6.49 GF1.B60 ; GF1.B110 122.65,6.49 v1(122.17,6.97) v1(122.17,8.03) ; v1(37.17,8.03) v1(37.17,6.97) 37.65,6.49 GF1.B25 ; GF1.B69 81.65,6.45 v1(82.17,6.96) v1(82.17,8.03) ; v1(114.17,8.03) v1(114.17,6.97) 114.65,6.49 GF1.B102 ; v1(17.12,6.97) 17.12,6.59 17.65,6.06 GF1.B7 ; v1(108.17,8.03) v1(108.17,6.96) 107.65,6.45 GF1.B95 ; v1(74.17,8.03) v1(74.17,6.96) 73.65,6.45 GF1.B61 ; v1(100.17,8.03) v1(100.17,6.96) 99.65,6.45 GF1.B87 ; v1(68.17,8.03) v1(68.17,6.97) 68.65,6.49 GF1.B56 ; v1(49.17,8.03) v1(49.17,6.96) 48.65,6.45 GF1.B36
  TOP w1.016: CFGCN1.4 v2(121.22,71.7) ; CFGCN1.2 v2(118.68,71.72)
  L3 w0.508: CN1.B44 73.83,49.38 ; CN1.B44 72.47,49.38 ; CN1.B44 72.47,50.74 ; CN1.B44 73.83,50.74 ; CN1.A41 70.83,53.88 ; CN1.A41 70.83,55.24 ; CN1.A41 69.47,55.24 ; CN1.A41 69.47,53.88 ; 59.47,53.88 CN1.A31 ; CN1.A31 59.47,55.24 ; CN1.A31 60.83,53.88 ; CN1.A31 60.83,55.24 ; 73.47,55.24 CN1.A45 ; CN1.A45 74.83,53.88 ; CN1.A45 74.83,55.24 ; CN1.A45 73.47,53.88 ; 71.47,51.38 CN1.B43 ; CN1.B43 72.83,52.74 ; CN1.B43 71.47,52.74 ; CN1.B43 72.83,51.38 ; 50.47,50.74 CN1.B22 ; CN1.B22 50.47,49.38 ; CN1.B22 51.83,49.38 ; CN1.B22 51.83,50.74 ; 75.47,51.38 CN1.B47 ; CN1.B47 75.47,52.74 ; CN1.B47 76.83,51.38 ; CN1.B47 76.83,52.74 ; H2.1 8.45,65.41 ; H2.1 8.45,60.51 ; H2.1 3.55,60.51 ; H2.1 3.55,65.41 ; CN1.A37 66.83,55.24 ; CN1.A37 66.83,53.88 ; CN1.A37 65.47,53.88 ; CN1.A37 65.47,55.24 ; 48.47,57.24 CN1.A20 ; CN1.A20 49.83,55.88 ; CN1.A20 48.47,55.88 ; CN1.A20 49.83,57.24 ; 130.85,65.51 H1.1 ; H1.1 135.75,65.51 ; H1.1 130.85,70.41 ; H1.1 135.75,70.41 ; 62.47,57.24 CN1.A34 ; CN1.A34 62.47,55.88 ; CN1.A34 63.83,57.24 ; CN1.A34 63.83,55.88 ; 116.39,41.49 CN3.4 ; CN3.4 118.81,43.91 ; CN3.4 116.39,43.91 ; CN3.4 118.81,41.49 ; 53.47,52.74 CN1.B25 ; CN1.B25 54.83,51.38 ; CN1.B25 53.47,51.38 ; CN1.B25 54.83,52.74 ; 77.47,53.88 CN1.A49 ; CN1.A49 77.47,55.24 ; CN1.A49 78.83,55.24 ; 70.47,57.24 CN1.A42 ; CN1.A42 70.47,55.88 ; CN1.A42 71.83,55.88 ; CN1.A42 71.83,57.24 ; 67.47,52.74 CN1.B39 ; CN1.B39 67.47,51.38 ; CN1.B39 68.83,52.74 ; CN1.B39 68.83,51.38 ; 64.47,50.74 CN1.B36 ; CN1.B36 65.83,49.38 ; CN1.B36 64.47,49.38 ; CN1.B36 65.83,50.74 ; CN1.B40 69.83,50.74 ; CN1.B40 68.47,49.38 ; CN1.B40 68.47,50.74 ; CN1.B40 69.83,49.38 ; CN1.A46 75.83,55.88 ; CN1.A46 74.47,57.24 ; CN1.A46 75.83,57.24 ; CN1.A46 74.47,55.88 ; CN3.1 118.81,54.09 ; CN3.1 118.81,56.51 ; CN3.1 116.39,56.51 ; CN3.1 116.39,54.09 ; 116.39,52.31 CN3.2 ; CN3.2 118.81,52.31 ; CN3.2 116.39,49.89 ; CN3.2 118.81,49.89 ; CN1.A23 52.83,55.24 ; CN1.A23 51.47,55.24 ; CN1.A23 51.47,53.88 ; CN1.A23 52.83,53.88 ; CN1.A24 53.83,57.24 ; CN1.A24 53.83,55.88 ; CN1.A24 52.47,55.88 ; CN1.A24 52.47,57.24 ; 66.47,57.24 CN1.A38 ; CN1.A38 67.83,55.88 ; CN1.A38 66.47,55.88 ; CN1.A38 67.83,57.24 ; 47.83,50.74 CN1.B18 47.83,49.38 ; 63.47,52.74 CN1.B35 ; CN1.B35 64.83,52.74 ; CN1.B35 64.83,51.38 ; CN1.B35 63.47,51.38 ; 77.47,52.74 CN1.B49 ; CN1.B49 77.47,51.38 ; CN1.B49 78.83,51.38 ; 47.83,57.24 CN1.A18 47.83,55.88 ; CN3.3 118.81,48.11 ; CN3.3 116.39,45.69 ; CN3.3 118.81,45.69 ; CN3.3 116.39,48.11 ; 61.83,49.38 CN1.B32 61.83,50.74 ; 49.47,51.38 CN1.B21 ; CN1.B21 50.83,51.38 ; CN1.B21 49.47,52.74 ; CN1.B21 50.83,52.74
  L4VCC w0.508: 3.55,65.41 H2.1 ; H2.1 8.45,60.51 ; H2.1 8.45,65.41 ; H2.1 3.55,60.51 ; H1.1 135.75,65.51 ; H1.1 130.85,70.41 ; H1.1 135.75,70.41 ; H1.1 130.85,65.51
  BOTTOM w0.508: 3.55,60.51 H2.1 ; H2.1 8.45,60.51 ; H2.1 3.55,65.41 ; H2.1 8.45,65.41 ; 130.85,70.41 H1.1 ; H1.1 135.75,65.51 ; H1.1 135.75,70.41 ; H1.1 130.85,65.51
  BOTTOM w0.635: GF1.A66 78.65,6.48 v1(78.17,6.96) v1(78.17,8.03) ; v1(100.17,8.03) v1(100.17,6.96) 100.65,6.48 GF1.A88 ; GF1.A12 24.65,5.73 25.25,6.33 25.25,7.6 v1(25.82,8.17) v1(25.82,9.27) ; v1(35.17,8.03) v1(35.17,6.96) 35.65,6.48 GF1.A23 ; v1(55.17,6.97) 54.65,6.44 GF1.A42 ; v1(104.17,8.03) v1(104.17,6.96) 104.65,6.48 GF1.A92 ; GF1.A27 39.65,6.48 v1(39.17,6.96) v1(39.17,8.03) ; GF1.A75 87.65,6.44 v1(88.17,6.97) v1(88.17,8.03) ; GF1.A104 116.65,6.48 v1(116.17,6.96) v1(116.17,8.03) ; v1(42.98,6.96) 43.65,6.29 GF1.A31 ; v1(102.17,8.03) v1(102.17,6.97) 101.65,6.44 GF1.A89 ; v1(59.17,6.97) 58.65,6.44 GF1.A46 ; v1(108.17,8.03) v1(108.17,6.96) 108.65,6.48 GF1.A96 ; GF1.A28 40.65,6.44 v1(41.17,6.97) v1(41.17,8.03) ; GF1.A51 63.65,6.13 64.19,6.66 v1(64.19,6.96) ; GF1.A4 14.65,6.19 15.34,6.89 v1(15.34,6.96) v1(15.34,8.03) ; v1(124.1,8.03) v1(124.1,6.96) 124.65,6.41 GF1.A112 ; v1(118.17,8.03) v1(118.17,6.97) 117.65,6.44 GF1.A105 ; v1(66.17,8.03) v1(66.17,6.96) 66.65,6.48 GF1.A54 ; v1(47.17,6.96) 46.65,6.44 GF1.A34 ; v1(68.17,8.03) v1(68.17,6.97) 67.65,6.44 GF1.A55 ; GF1.A41 53.65,6.48 v1(53.17,6.96) ; GF1.A93 105.65,6.44 v1(106.17,6.97) v1(106.17,8.03) ; GF1.A1 11.65,10.15 v2(12.08,10.57) ; GF1.A79 91.65,6.44 v1(92.17,6.97) v1(92.17,8.03) ; v1(84.17,8.03) v1(84.17,6.97) 83.65,6.44 GF1.A71 ; v1(62.15,6.96) 61.65,6.46 GF1.A49 ; GF1.A24 36.65,6.44 v1(37.17,6.97) v1(37.17,8.03) ; v1(120.17,8.03) v1(120.17,6.96) 120.65,6.48 GF1.A108 ; v1(31.17,6.96) v1(31.17,8.03) ; v1(31.17,6.96) 30.65,6.45 GF1.A18 ; v1(31.17,6.96) 31.65,6.48 GF1.A19 ; v1(82.17,8.03) v1(82.17,6.96) 82.65,6.48 GF1.A70 ; GF1.A45 57.65,6.48 v1(57.17,6.96) ; GF1.A62 74.65,6.48 v1(74.17,6.96) v1(74.17,8.03) ; v1(33.17,8.03) v1(33.17,6.97) 32.65,6.44 GF1.A20 ; v1(110.17,8.03) v1(110.17,6.97) 109.65,6.44 GF1.A97 ; v1(80.17,8.03) v1(80.17,6.97) 79.65,6.44 GF1.A67 ; v1(90.17,8.03) v1(90.17,6.96) 90.65,6.48 GF1.A78 ; GF1.A59 71.65,6.44 v1(72.17,6.97) v1(72.17,8.03) ; GF1.A115 127.65,5.69 127.15,6.18 127.15,10.29 v1(125.68,11.77) ; GF1.A85 97.65,6.44 v1(98.17,6.97) v1(98.17,8.03) ; GF1.A109 121.65,6.44 v1(122.17,6.97) v1(122.17,8.03) ; GF1.A100 112.65,6.48 v1(112.17,6.96) v1(112.17,8.03) ; GF1.A15 27.65,6.47 v1(28.14,6.96) v1(28.14,8.03) ; v1(49.17,8.03) v1(49.17,6.96) 49.65,6.48 GF1.A37 ; GF1.A38 50.65,6.44 v1(51.17,6.97) ; GF1.A7 17.65,6.44 v1(17.12,6.97) ; GF1.A74 86.65,6.48 v1(86.17,6.96) v1(86.17,8.03) ; GF1.A82 94.65,6.27 94.61,6.32 94.61,6.62 v1(94.26,6.96) ; GF1.A63 75.65,6.44 v1(76.17,6.97) v1(76.17,8.03) ; GF1.A101 113.65,6.44 v1(114.17,6.97) v1(114.17,8.03) ; GF1.A58 70.65,6.48 v1(70.17,6.96) v1(70.17,8.03) ; GF1.A84 96.65,6.48 v1(96.17,6.96) v1(96.17,8.03)
  vias: v1(16.27,64.75) v1(16.33,61.19) v1(17.59,64.72) v1(17.65,61.16) v1(18.92,64.69) v1(18.98,61.13) v1(27.48,42.45) v1(27.62,41.1) v1(28.89,42.46) v1(28.92,41.1) v1(30.21,42.43) v1(30.15,41.09) v1(33.18,61.36) v1(33.34,60.23) v1(34.6,61.37) v1(34.64,60.23) v1(35.91,61.35) v1(35.87,60.21) v1(47.54,59.59) v1(47.63,63.24) v1(48.93,63.24) v1(48.96,59.6) v1(50.16,63.23) v1(50.27,59.57) v2(1.99,76) v2(1.99,72.19) v2(1.99,68.38) v2(2.52,58.41) v2(2.57,55.09) v2(2.63,50.76) v2(2.68,47.45) v2(2.85,44.25) v2(2.9,40.94) v2(3.03,37.34) v2(3.09,34.03) v2(5.38,69) v2(5.8,76) v2(5.8,72.19) v2(6.38,55.09) v2(6.9,34.03) v2(9.61,76) v2(9.61,72.19) v2(9.61,68.38) v2(17.87,36.98) v2(17.87,33.17) v2(17.87,29.36) v2(21.68,36.98) v2(21.68,33.17) v2(21.71,29.99) v2(25.49,36.98) v2(25.49,33.17) v2(30.19,36.9) v2(33.64,20.02) v2(39.5,64.41) v2(39.71,12.89) v2(40.92,64.28) v2(40.97,58.96) v2(43.57,30.47) v2(43.83,35.5) v2(44.31,15.83) v2(48.57,35.32) v2(48.9,15.72) v2(50.12,22.3) v2(53.35,41.68) v2(53.61,13.37) v2(54.12,27.97) v2(54.35,19.43) v2(55.6,25.76) v2(56,34.55) v2(57.36,13.62) v2(58.17,19.73) v2(60.27,28.48) v2(61.81,35.76) v2(64.35,13.92) v2(65.6,25.94) v2(65.89,30.8) v2(67.03,18.44) v2(67.96,39.23) v2(70.19,23.07) v2(70.78,35.43) v2(72.25,13.4) v2(73.1,26.97) v2(74.94,29.8) v2(75.94,36.11) v2(76.19,11.75) v2(76.7,33.22) v2(76.92,16.35) v2(78.58,41.9) v2(79.75,36.11) v2(80.16,12.89) v2(80.45,19.69) v2(83.87,15.39) v2(85.12,22.56) v2(90.97,29.29) v2(92.66,22.3) v2(94.02,16.05) v2(104.72,12.45) v2(106.3,27.63) v2(107.96,55.18) v2(108.29,12.89) v2(108.52,42.81) v2(108.47,39.81) v2(110.31,16.53) v2(110.39,21.31) v2(110.53,25.72) v2(111.31,74.86) v2(111.87,64.81) v2(112.66,69.15) v2(113.07,33.63) v2(113.12,30.31) v2(113.31,38.23) v2(114.19,76.8) v2(114.54,60.58) v2(115.68,64.81) v2(115.75,69.16) v2(115.86,18.63) v2(115.86,12.71) v2(116.2,26.72) v2(116.25,23.4) v2(116.59,76.78) v2(116.65,73.47) v2(116.67,38.15) v2(116.88,33.63) v2(116.93,30.31) v2(120,59.95) v2(120.01,26.72) v2(120.06,23.4) v2(120.4,76.78) v2(120.46,73.47) v2(120.63,36.94) v2(120.69,33.63) v2(120.74,30.31) v2(121.49,18.26) v2(122.55,64.76) v2(122.61,69.11) v2(123.82,26.72) v2(123.84,13.48) v2(123.87,23.4) v2(124.21,76.78) v2(124.27,73.47) v2(124.99,50.98) v2(125.12,47.08) v2(125.84,37.16) v2(126.01,33.85) v2(126.42,69.11) v2(126.36,64.76) v2(128.65,59.8) v2(128.61,44.41) v2(128.74,40.51) v2(128.78,55.9) v2(128.8,50.98) v2(128.93,47.08) v2(129.29,76.78) v2(129.35,73.47) v2(131.77,36.86) v2(131.82,33.55) v2(132.12,40.3) v2(132.21,62.96) v2(132.26,59.65) v2(132.61,50.98) v2(132.58,44.5) v2(132.67,47.67) v2(132.84,55.99) v2(133.1,76.78) v2(133.16,73.47) v2(135.58,36.86) v2(135.63,33.55) v2(135.93,40.3) v2(136.02,62.96) v2(136.07,59.65) v2(136.42,50.98) v2(136.39,44.5) v2(136.48,47.67) v2(136.65,55.99) v2(136.91,76.78) v2(136.97,73.47)
P3V3: length 17.6
  TOP w0.508: CN2.A9 36.15,75.44 v2(36.08,75.37) ; CN2.A10 v2(37.15,75.35) ; CN2.B8 v2(35.15,71.98)
  L3 w0.508: CN1.A10 37.83,55.88 ; CN1.A10 36.47,55.88 ; CN1.A10 37.83,57.24 ; CN1.A10 36.47,57.24 ; 34.47,49.38 CN1.B8 ; CN1.B8 34.47,50.74 ; CN1.B8 35.83,50.74 ; CN1.B8 35.83,49.38 ; 35.47,55.24 CN1.A9 ; CN1.A9 36.83,53.88 ; CN1.A9 35.47,53.88 ; CN1.A9 36.83,55.24
  vias: v1(18.36,14.08) v1(18.36,12.53) v1(18.87,11.31) v1(19.18,13.27) v1(20.02,14.05) v1(20.04,12.48) v1(32.72,42.44) v1(32.83,45.65) v1(34.2,45.67) v1(34.17,42.43) v1(35.5,45.65) v1(35.56,42.47) v1(42.24,59.89) v1(42.32,63.34) v1(43.62,63.34) v1(43.65,59.91) v1(44.85,63.32) v1(44.97,59.88) v2(36.23,73.75)
P3V3_AUX: length 32.4
  TOP w0.356: C20.1 21.7,42.98 U8.5
  TOP w0.508: CN1.B10 37.83,49.38 ; CN1.B10 36.47,49.38 ; CN1.B10 36.47,50.74 ; CN1.B10 37.83,50.74 ; C20.1 21.7,39.41 v2(21.73,39.38)
  BOTTOM w0.508: v2(21.73,39.38) 21.81,39.3 34.71,39.3 36.72,41.31 37.24,41.83 37.24,49.93 37.15,50.02 CN1.B10
P5V-1: length 3.6
  TOP w1.016: TP4.1 112.1,56.15 CN3.5
P5V-2: length 3.5
  TOP w1.016: TP5.1 110.55,45.35 CN3.7
P12V: length 122.5
  TOP w0.508: CN3.8 113.31,41.49 ; CN3.8 110.89,43.91 ; CN3.8 110.89,41.49 ; CN3.8 113.31,43.91 ; 29.62,75.29 29.15,75.76 CN2.A2 ; 29.62,75.29 29.63,75.29 v2(29.66,75.26) ; 29.62,75.29 30.15,75.82 CN2.A3 ; 29.47,53.88 CN1.A3 ; CN1.A3 30.83,55.24 ; CN1.A3 30.83,53.88 ; CN1.A3 29.47,55.24 ; 29.47,51.38 CN1.B3 ; CN1.B3 30.83,52.74 ; CN1.B3 30.83,51.38 ; CN1.B3 29.47,52.74 ; 110.89,49.89 CN3.6 ; CN3.6 113.31,49.89 ; CN3.6 113.31,52.31 ; CN3.6 110.89,52.31 ; CN1.B1 28.83,52.74 ; CN1.B1 27.47,51.38 ; CN1.B1 28.83,51.38 ; CN1.B1 27.47,52.74 ; 28.47,49.38 CN1.B2 ; CN1.B2 29.83,50.74 ; CN1.B2 28.47,50.74 ; CN1.B2 29.83,49.38 ; 28.47,55.88 CN1.A2 ; CN1.A2 28.47,57.24 ; CN1.A2 29.83,57.24 ; CN1.A2 29.83,55.88
  L3 w0.508: CN1.B2 29.83,49.38 ; CN1.B2 28.47,50.74 ; CN1.B2 29.83,50.74 ; CN1.B2 28.47,49.38 ; 29.47,51.38 CN1.B3 ; CN1.B3 29.47,52.74 ; CN1.B3 30.83,51.38 ; CN1.B3 30.83,52.74 ; 28.47,55.88 CN1.A2 ; CN1.A2 29.83,55.88 ; CN1.A2 29.83,57.24 ; CN1.A2 28.47,57.24 ; 27.47,52.74 CN1.B1 ; CN1.B1 27.47,51.38 ; CN1.B1 28.83,52.74 ; CN1.B1 28.83,51.38 ; 29.47,55.24 CN1.A3 ; CN1.A3 30.83,55.24 ; CN1.A3 30.83,53.88 ; CN1.A3 29.47,53.88
  L4VCC w0.508: CN3.6 113.31,52.31 ; CN3.6 110.89,49.89 ; CN3.6 110.89,52.31 ; CN3.6 113.31,49.89 ; 28.47,55.88 CN1.A2 ; CN1.A2 28.47,57.24 ; CN1.A2 29.83,57.24 ; CN1.A2 29.83,55.88 ; CN1.B1 28.83,52.74 ; CN1.B1 28.83,51.38 ; CN1.B1 27.47,51.38 ; CN1.B1 27.47,52.74 ; CN1.B3 30.83,51.38 ; CN1.B3 29.47,51.38 ; CN1.B3 29.47,52.74 ; CN1.B3 30.83,52.74 ; CN1.B2 29.83,49.38 ; CN1.B2 28.47,49.38 ; CN1.B2 29.83,50.74 ; CN1.B2 28.47,50.74 ; 110.89,43.91 CN3.8 ; CN3.8 113.31,41.49 ; CN3.8 110.89,41.49 ; CN3.8 113.31,43.91 ; CN1.A3 30.83,53.88 ; CN1.A3 29.47,53.88 ; CN1.A3 29.47,55.24 ; CN1.A3 30.83,55.24
  BOTTOM w0.508: 28.47,49.38 CN1.B2 ; CN1.B2 29.83,50.74 ; CN1.B2 29.83,49.38 ; CN1.B2 28.47,50.74 ; 110.89,52.31 CN3.6 ; CN3.6 110.89,49.89 ; CN3.6 113.31,52.31 ; CN3.6 113.31,49.89 ; CN3.8 113.31,41.49 ; CN3.8 110.89,41.49 ; CN3.8 113.31,43.91 ; CN3.8 110.89,43.91 ; CN1.A2 29.83,57.24 ; CN1.A2 28.47,57.24 ; CN1.A2 28.47,55.88 ; CN1.A2 29.83,55.88 ; 27.47,51.38 CN1.B1 ; CN1.B1 28.83,51.38 ; CN1.B1 27.47,52.74 ; CN1.B1 28.83,52.74 ; CN1.B3 30.83,51.38 ; CN1.B3 29.47,52.74 ; CN1.B3 30.83,52.74 ; CN1.B3 29.47,51.38 ; 29.47,55.24 CN1.A3 ; CN1.A3 30.83,53.88 ; CN1.A3 29.47,53.88 ; CN1.A3 30.83,55.24
  vias: v1(12.82,9.54) v1(13.07,26.87) v1(13.21,31.19) v1(13.22,21.54) v1(13.23,11.69) v1(13.34,74.85) v1(13.29,71.45) v1(13.28,10.58) v1(13.37,67.78) v1(13.37,8.35) v1(13.42,7.21) v1(13.94,9.53) v1(14.04,53.11) v1(14.06,56.48) v1(14.31,11.73) v1(14.39,10.64) v1(15.6,71.47) v1(15.56,26.86) v1(15.65,74.86) v1(15.68,67.8) v1(16.04,31.09) v1(16.25,21.55) v1(16.54,53.28) v1(16.57,56.65) v1(18.44,71.44) v1(18.49,74.83) v1(18.51,67.77) v1(18.67,35.2) v1(18.84,56.66) v1(18.81,53.29) v1(20.26,49.05) v1(21.16,35.18) v1(22.22,49.04) v1(22.39,61.13) v1(22.39,59.83) v1(22.46,65.73) v1(22.46,64.5) v1(23.63,61.12) v1(23.63,59.82) v1(23.71,65.72) v1(23.71,64.49) v1(24.36,49.01) v1(24.88,61.11) v1(24.88,59.81) v1(24.96,65.71) v1(24.96,64.48) v1(26.16,35.34) v1(27.21,65.86) v1(27.26,64.62) v1(27.33,59.88) v1(27.36,61.17) v1(28.08,72.94) v1(28.45,65.86) v1(28.5,64.62) v1(28.6,61.16) v1(28.58,59.87) v1(28.65,35.33) v1(28.85,72.04) v1(28.92,73.82) v1(29.7,65.85) v1(29.75,64.61) v1(29.83,59.86) v1(29.91,72.88) v1(29.85,61.15) v1(112.92,57.89) v1(113.29,40.14) v1(114.17,57.89) v1(114.53,40.13) v1(115.42,57.88) v1(115.78,40.12)
CLK100_PCIE_SLOT0_N: length 65.6
  BOTTOM w0.165: GF1.A6 16.65,5.75 16.29,6.11 16.29,11.95 16.88,15.3 19.04,17.8 19.41,19.84 19.43,25.01 19.68,25.81 21.45,27.36 33.72,34.28 38.97,40.21 40.01,41.76 41.66,44.25 41.88,46.17 41.89,46.29 42.3,49.81 42.29,49.96 42.29,50.48 42.47,50.81 42.82,51.06 43.28,51.69 43.28,52.05 43.28,52.44 43.29,54.61 43.13,55.47 42.86,55.61 42.79,55.83 CN1.A14
CLK100_PCIE_SLOT0_P: length 65.6
  BOTTOM w0.165: GF1.A5 15.65,5.75 16.01,6.11 16.01,11.98 16.62,15.42 18.77,17.93 19.13,19.86 19.15,25.05 19.43,25.96 21.29,27.59 23.58,28.88 33.54,34.5 34.11,35.14 38.75,40.38 39.77,41.92 41.39,44.35 41.6,46.21 41.5,46.33 41.56,46.82 41.68,46.92 41.74,47.41 41.64,47.54 41.7,48.03 41.82,48.13 41.88,48.62 41.78,48.74 41.84,49.23 41.96,49.33 42.02,49.82 42.01,50.55 42.26,51 42.62,51.26 43,51.78 43,52.05 43,52.44 43.01,54.59 42.88,55.29 42.74,55.36 42.51,55.29 CN1.A13
CLK100_PCIE_SLOT1_N: length 92.2
  TOP w0.165: v2(43.14,74.94) 42.79,75.29 42.79,75.71 43.15,76.07 CN2.A14
  BOTTOM w0.165: GF1.A33 45.65,5.75 45.29,6.11 45.29,6.28 45.58,7.94 58.48,26.35 62.49,49.14 62.29,50.28 62.38,50.81 62.58,51 63.08,51.3 63.3,51.79 63.28,52.34 63.3,54.42 63.17,55.33 62.67,55.79 62.4,56.06 62.31,56.5 62.31,57 61.97,58.97 60.98,64.57 60.28,65.57 58.92,66.52 48.28,68.34 43.86,71.43 43.77,71.5 43.76,71.51 43.23,72.23 43.03,73.34 42.89,74.18 42.82,74.55 42.82,74.55 v2(43.14,74.94)
CLK100_PCIE_SLOT1_P: length 92.2
  TOP w0.165: v2(42.16,74.93) 42.51,75.28 42.51,75.71 42.15,76.07 CN2.A13
  BOTTOM w0.165: GF1.A32 44.65,5.75 45.01,6.11 45.01,6.3 45.32,8.05 58.21,26.46 62.21,49.14 62.01,50.28 62.12,50.94 62.4,51.22 62.86,51.5 63.02,51.84 63,52.34 63.02,54.4 62.91,55.19 62.48,55.59 62.14,55.93 62.04,56.47 62.04,56.98 61.69,58.92 60.72,64.46 60.08,65.37 58.81,66.26 48.17,68.08 43.82,71.12 43.7,71.2 43.56,71.3 42.97,72.12 42.76,73.29 42.61,74.13 42.55,74.5 v2(42.16,74.93)
CLK100_PCIE_SLOT_N: length 44.7
  BOTTOM w0.165: TP2.1 42.99,42.31 42.64,41.68 42.03,39.09 41.06,27.69 40.88,27.28 40.88,27.27 40.8,27.15 28.99,10.29 27.4,8.86 26.29,6.95 26.29,6.11 26.65,5.75 GF1.A14
CLK100_PCIE_SLOT_P: length 44.7
  BOTTOM w0.165: GF1.A13 25.65,5.75 26.01,6.11 26.01,7.03 26.81,8.39 27.16,9 27.18,9.04 28.78,10.48 28.79,10.49 40.63,27.39 40.78,27.76 41.75,39.11 41.75,39.13 42.38,41.78 42.75,42.45 TP1.1
LAN_SMB_ALERT_N: length 48.5
  TOP w0.191: RE4.2 45.24,42.69 RE8.2 45.24,41.56 v2(45.13,41.45) ; GF1.B12 24.65,5.66 25.02,6.03 25.02,10.78 v2(27.53,13.29)
  L3 w0.216: v2(27.53,13.29) 27.53,16.41 40.67,29.55 40.67,36.98 v2(45.13,41.45)
LAN_SMB_CLK: length 81.5
  TOP w0.191: RE2.1 58.1,59.96 57.82,59.67 57.5,59.67 57.16,60.01 v2(57.16,60.02) 56.86,59.72 56.53,59.72 RE5.1 ; v1(18.92,9.84) 18.99,9.84 19.65,9.18 GF1.B9
  L3 w0.216: v2(57.16,60.02) 56.9,59.76 56.44,59.76 56.01,59.34 56.01,56.04 56.72,55.33 56.73,55.3 56.82,55.16 56.89,55.09 57.01,54.97 57.01,53.97 56.99,53.92 56.96,53.76 56.96,53.68 56.96,52.94 56.96,52.85 56.99,52.69 57.01,52.64 57.01,51.76 55.96,50.71 55.96,49.29 56.42,48.83 56.42,39.68 29,12.26 23.6,12.26 23.33,12.26 20.5,9.42 19.34,9.42 v1(18.92,9.84)
LAN_SMB_DAT: length 80.2
  TOP w0.191: RE3.1 57.82,59.37 57.43,59.37 v2(57.16,59.1) 56.84,59.42 56.58,59.42 RE6.1
  L3 w0.216: v1(18.95,8.77) 19.28,9.09 20.63,9.09 23.47,11.93 29.14,11.93 56.75,39.54 56.75,48.97 56.29,49.43 56.29,50.58 57.34,51.63 57.34,52.71 57.31,52.77 57.31,52.78 57.29,52.88 57.29,52.93 57.29,53.68 57.29,53.73 57.31,53.83 57.34,53.91 57.34,55.11 57.12,55.32 57.08,55.37 57.03,55.45 57,55.51 56.35,56.17 56.35,59.2 56.58,59.43 56.83,59.43 v2(57.16,59.1)
  BOTTOM w0.191: GF1.A8 18.65,8.47 v1(18.95,8.77)
PCH_PLTRST_N: length 49.6
  TOP w0.191: U8.2 21.02,45.78 20.89,45.91 17.79,45.91 17.51,45.63 17.51,41.98 R5.1 16.69,39.55 20.27,35.97 20.27,25.87 21.08,25.06 v1(21.08,25.04)
  BOTTOM w0.191: GF1.A11 21.65,5.39 21.34,5.7 21.34,8.41 21.63,8.7 21.63,24.5 21.09,25.04 v1(21.08,25.04)
PCIE_CPRSNT_N: length 44.7
  TOP w0.191: GF1.B114 126.65,12.19 122.41,16.43 122.41,18.84 109.07,32.19 109.07,40.82 TP3.1
PCIE_SLOT0_CPRSNT1_N: length 60.7
  TOP w0.191: GF1.B17 29.65,7.6 30.76,10.19 32.25,11.89 32.25,13.23 v2(32.29,13.27)
  L3 w0.216: v2(32.29,13.27) 60.15,41.13 CN1.B31
PCIE_SLOT0_CPRSNT2_N: length 69.9
  TOP w0.191: v1(44.3,9.38) 43.65,8.73 GF1.B31
  L3 w0.216: v1(44.3,9.38) 45.09,10.18 61.6,10.18 61.93,10.51 61.93,31.09 77.15,46.31 CN1.B48
PCIE_SLOT0_RXN0: length 58
  BOTTOM w0.165: CN1.A48 76.79,55.83 76.86,55.61 77.13,55.47 77.29,54.63 77.28,52.05 77.11,51.25 76.61,50.81 76.35,50.48 76.32,50.05 76.36,46.42 76.37,45.58 74.05,32.41 61.82,14.94 60.29,6.28 60.29,6.11 60.65,5.75 GF1.A48
PCIE_SLOT0_RXN1: length 59
  BOTTOM w0.165: CN1.A44 72.86,55.98 72.86,55.61 72.86,55.61 73.13,55.47 73.29,54.63 73.28,52.57 73.28,51.85 73.29,51.84 73.57,51.3 74.06,50.95 74.29,50.49 74.66,46.82 74.74,46 72.46,33.09 57,11.01 56.29,6.97 56.29,6.11 56.65,5.75 GF1.A44
PCIE_SLOT0_RXN2: length 59.1
  BOTTOM w0.165: GF1.A40 52.65,5.75 52.29,6.11 52.29,7.08 52.57,8.69 68.04,30.77 70.92,47.12 70.43,49.15 70.41,49.28 70.34,50 70.29,50.49 70.06,50.95 69.57,51.3 69.28,51.85 69.28,52.05 69.28,52.44 69.29,54.89 69.19,55.24 69.12,55.48 68.86,55.61 68.86,55.61 68.79,55.83 CN1.A40
PCIE_SLOT0_RXN3: length 58.9
  BOTTOM w0.165: GF1.A36 48.65,5.75 48.29,6.11 48.29,7.75 48.36,8.14 63.39,29.6 66.57,47.68 66.3,50.43 66.29,50.49 66.06,50.95 65.57,51.3 65.28,51.85 65.28,52.05 65.28,52.44 65.28,52.44 65.32,54.71 65.12,55.48 64.86,55.61 64.79,55.83 CN1.A36
PCIE_SLOT0_RXN4: length 58.8
  BOTTOM w0.165: GF1.A30 42.65,5.75 42.29,6.11 42.29,7.52 42.62,9.41 57.08,30.05 60.43,49.09 60.29,50.49 60.06,50.95 59.57,51.3 59.28,51.85 59.28,52.05 59.28,52.44 59.32,54.62 59.13,55.48 58.86,55.61 58.79,55.83 CN1.A30
